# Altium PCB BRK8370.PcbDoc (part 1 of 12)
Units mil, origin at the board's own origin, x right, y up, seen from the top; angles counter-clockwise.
Board outline 8267.72 x 5708.66 mil, 6 copper layers (L1-TOP, L2-GND, L3-PWR, L4-PWR, L5-GND, L6-BOT), stack 68.606 mil thick; 319 components, 516 nets, 2008 pads, 1743 vias.
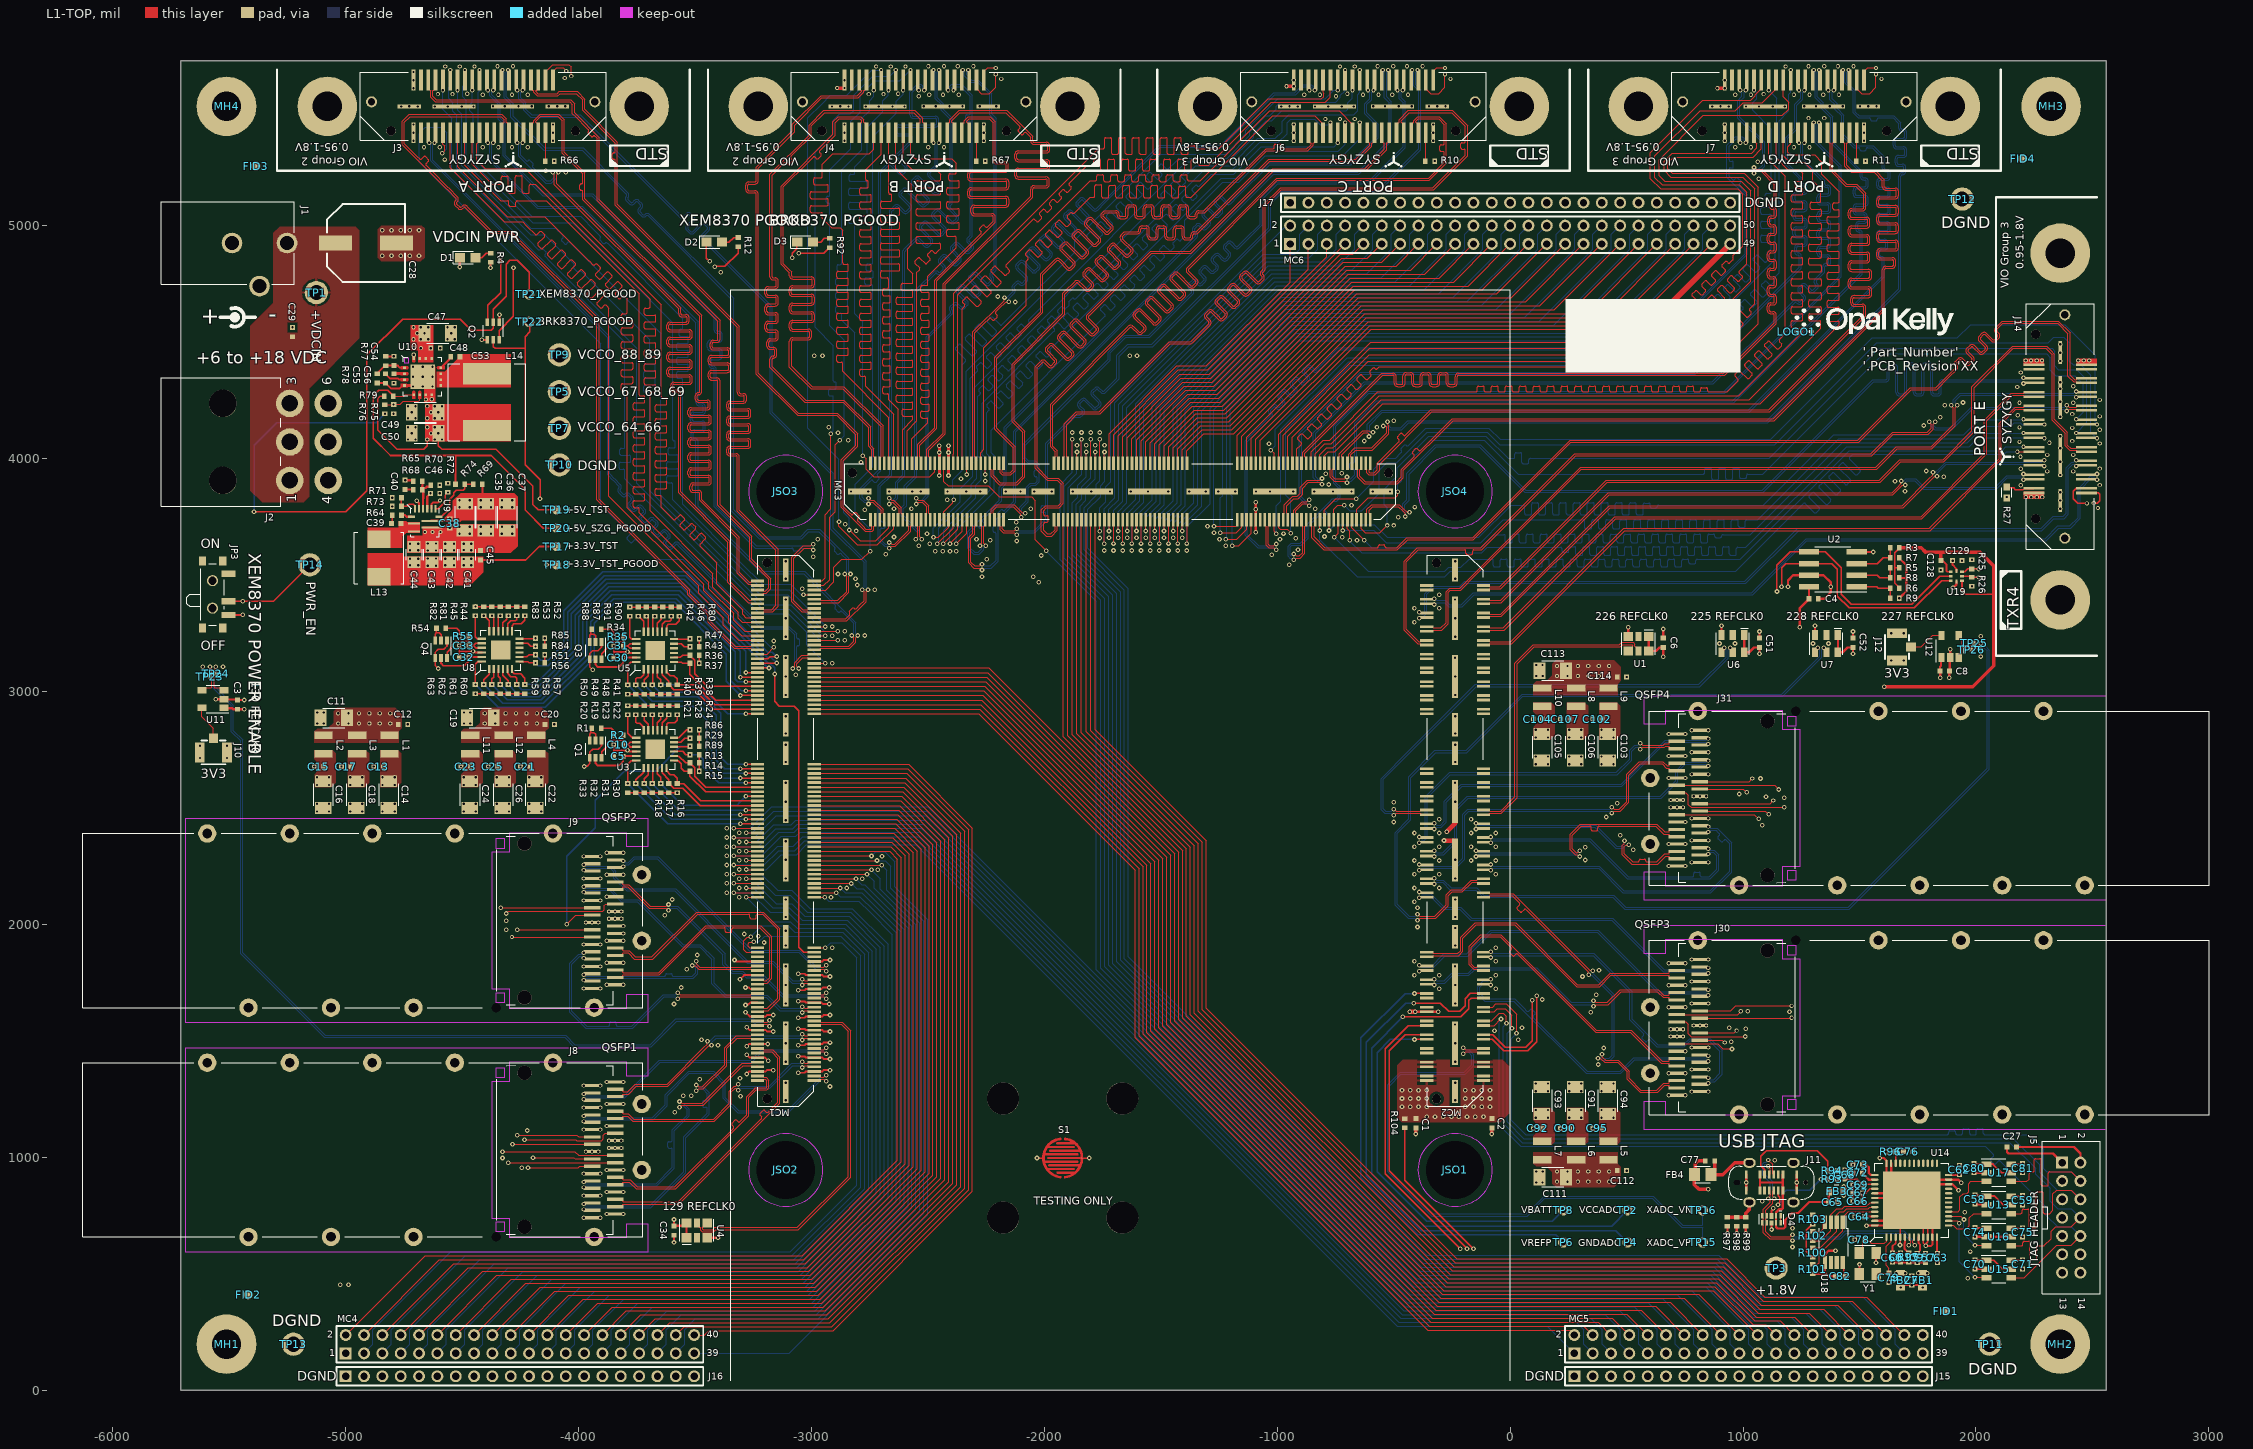
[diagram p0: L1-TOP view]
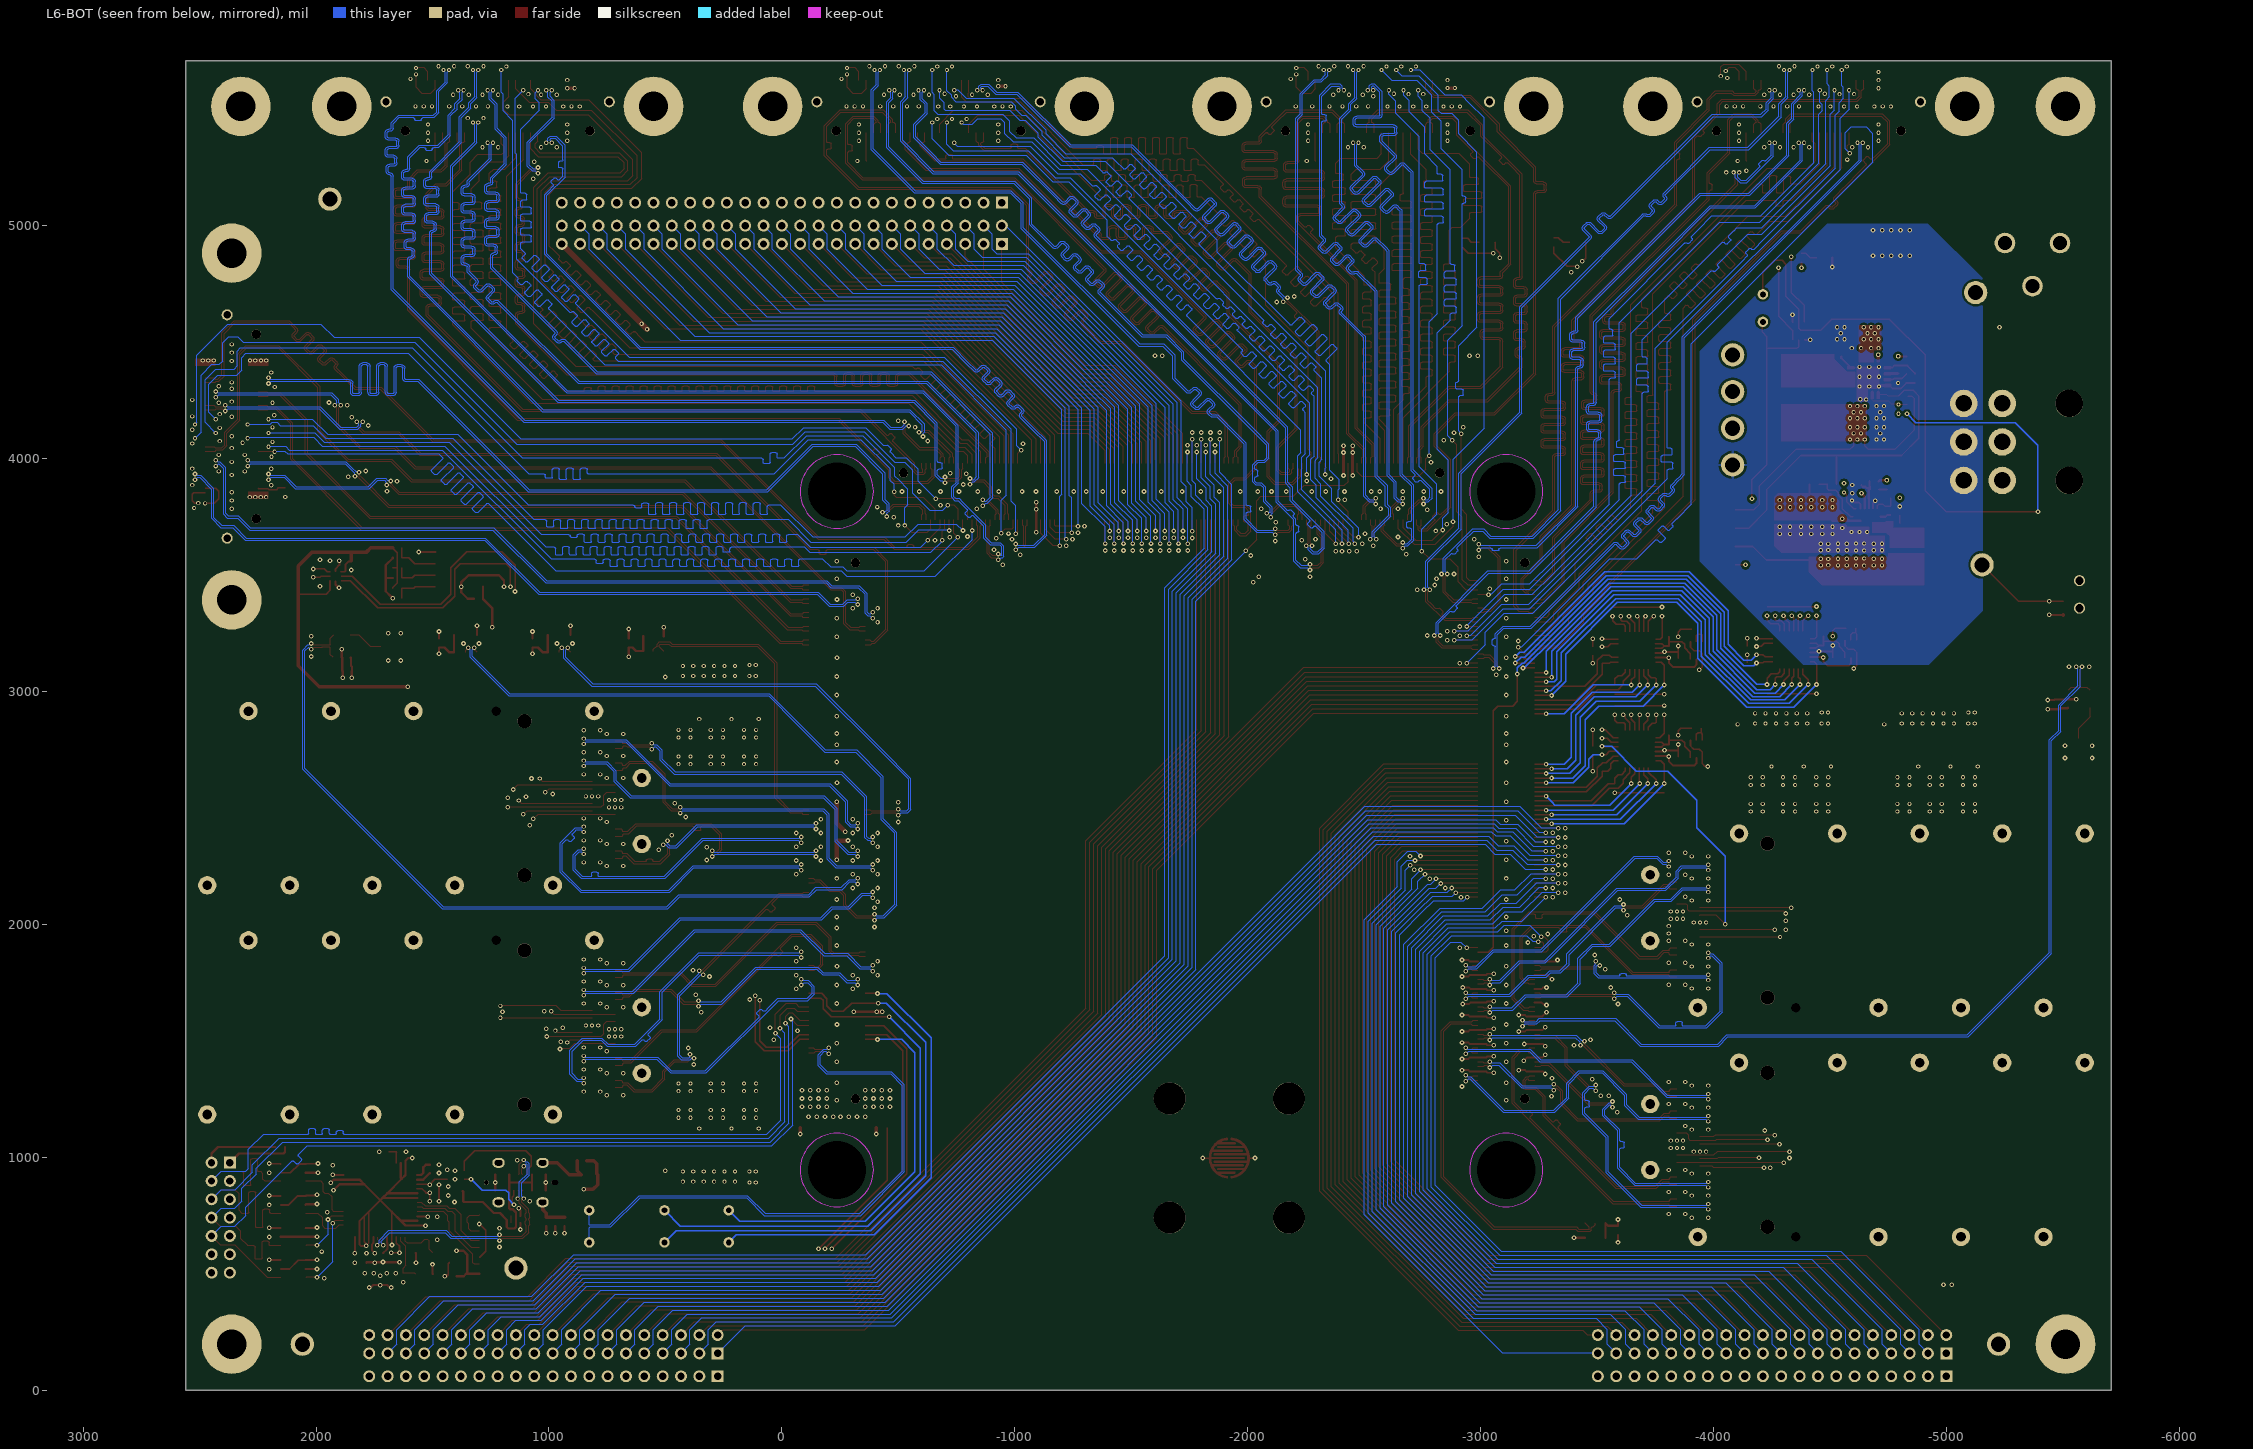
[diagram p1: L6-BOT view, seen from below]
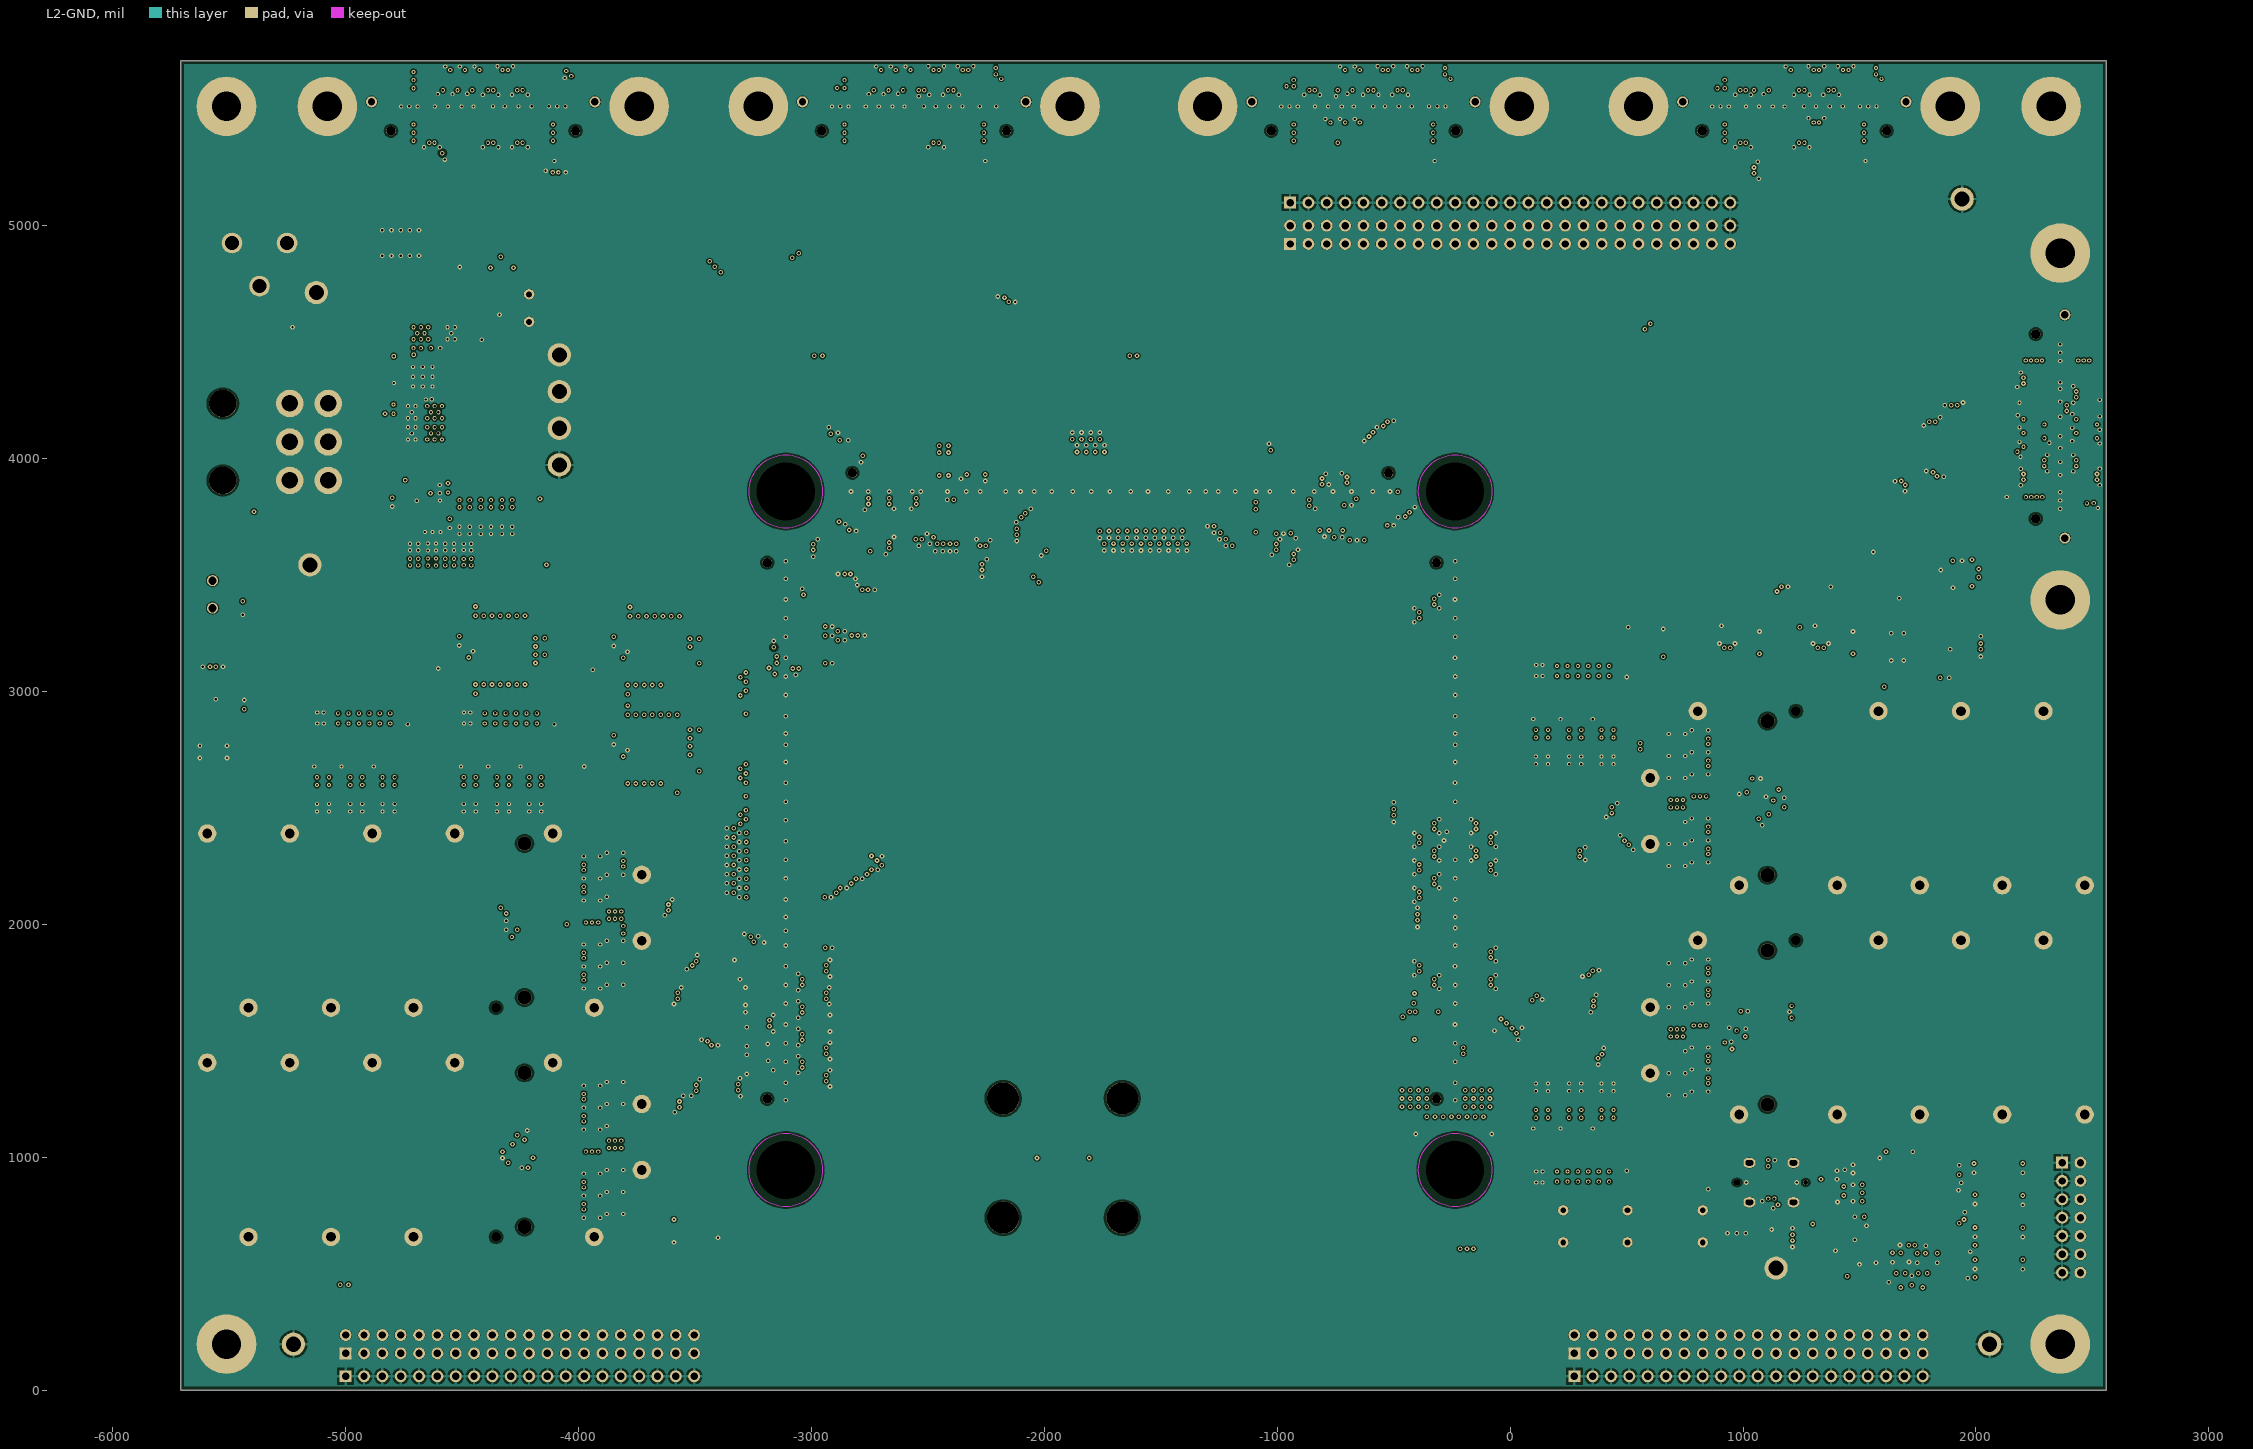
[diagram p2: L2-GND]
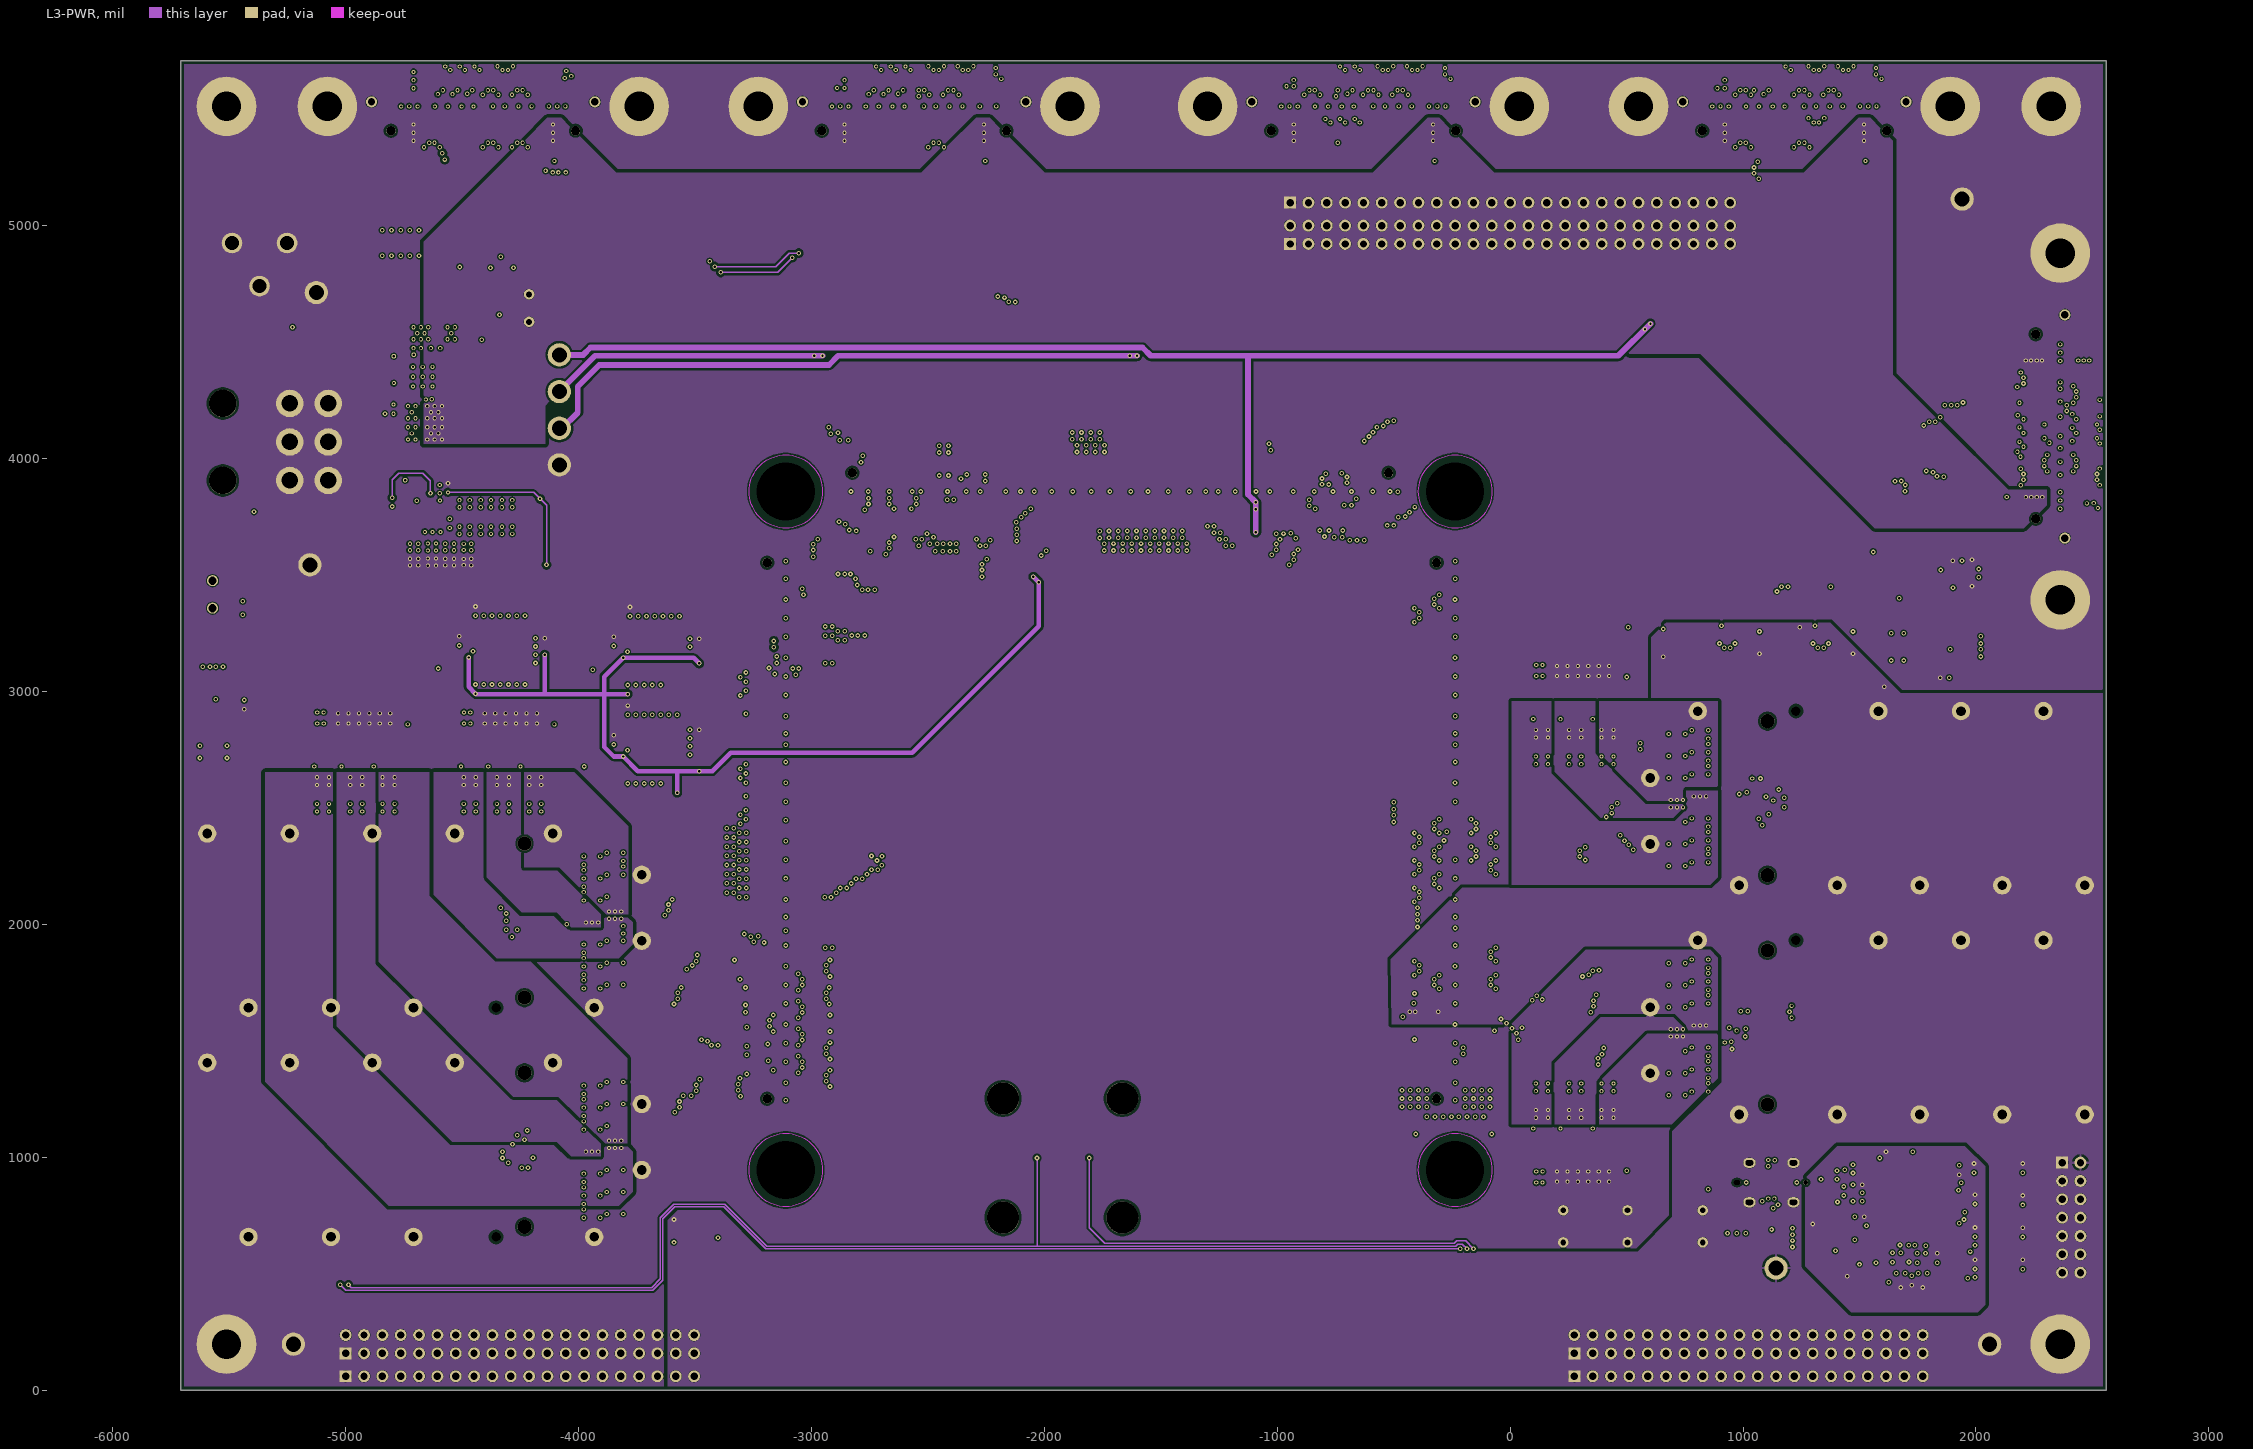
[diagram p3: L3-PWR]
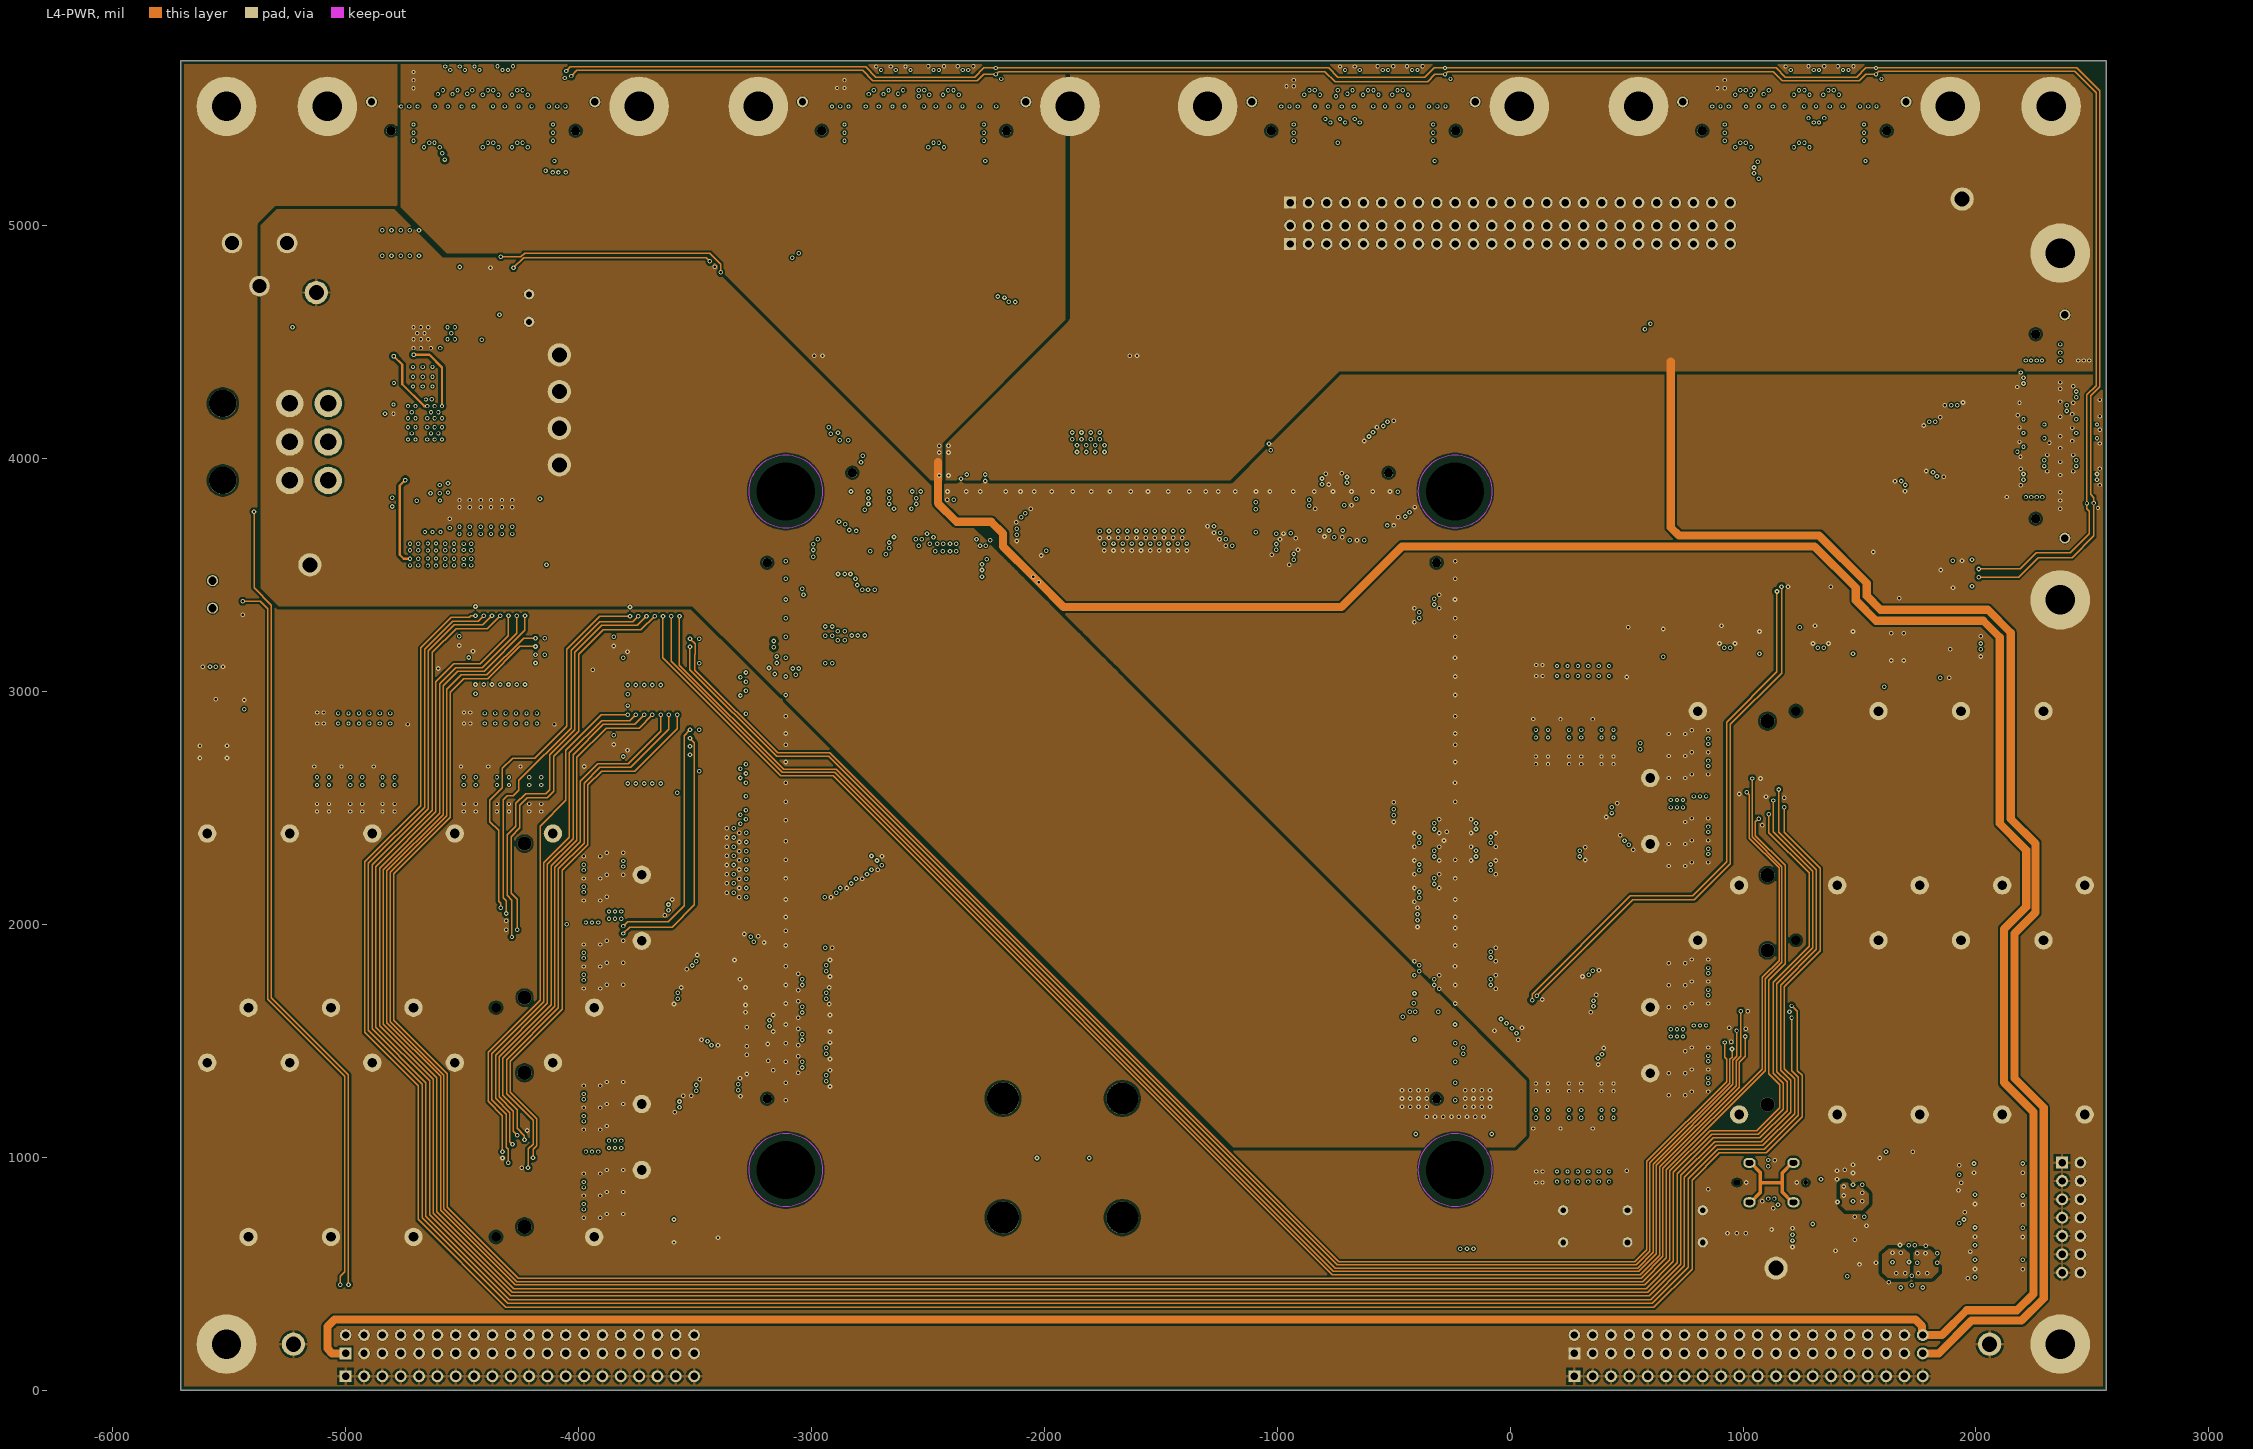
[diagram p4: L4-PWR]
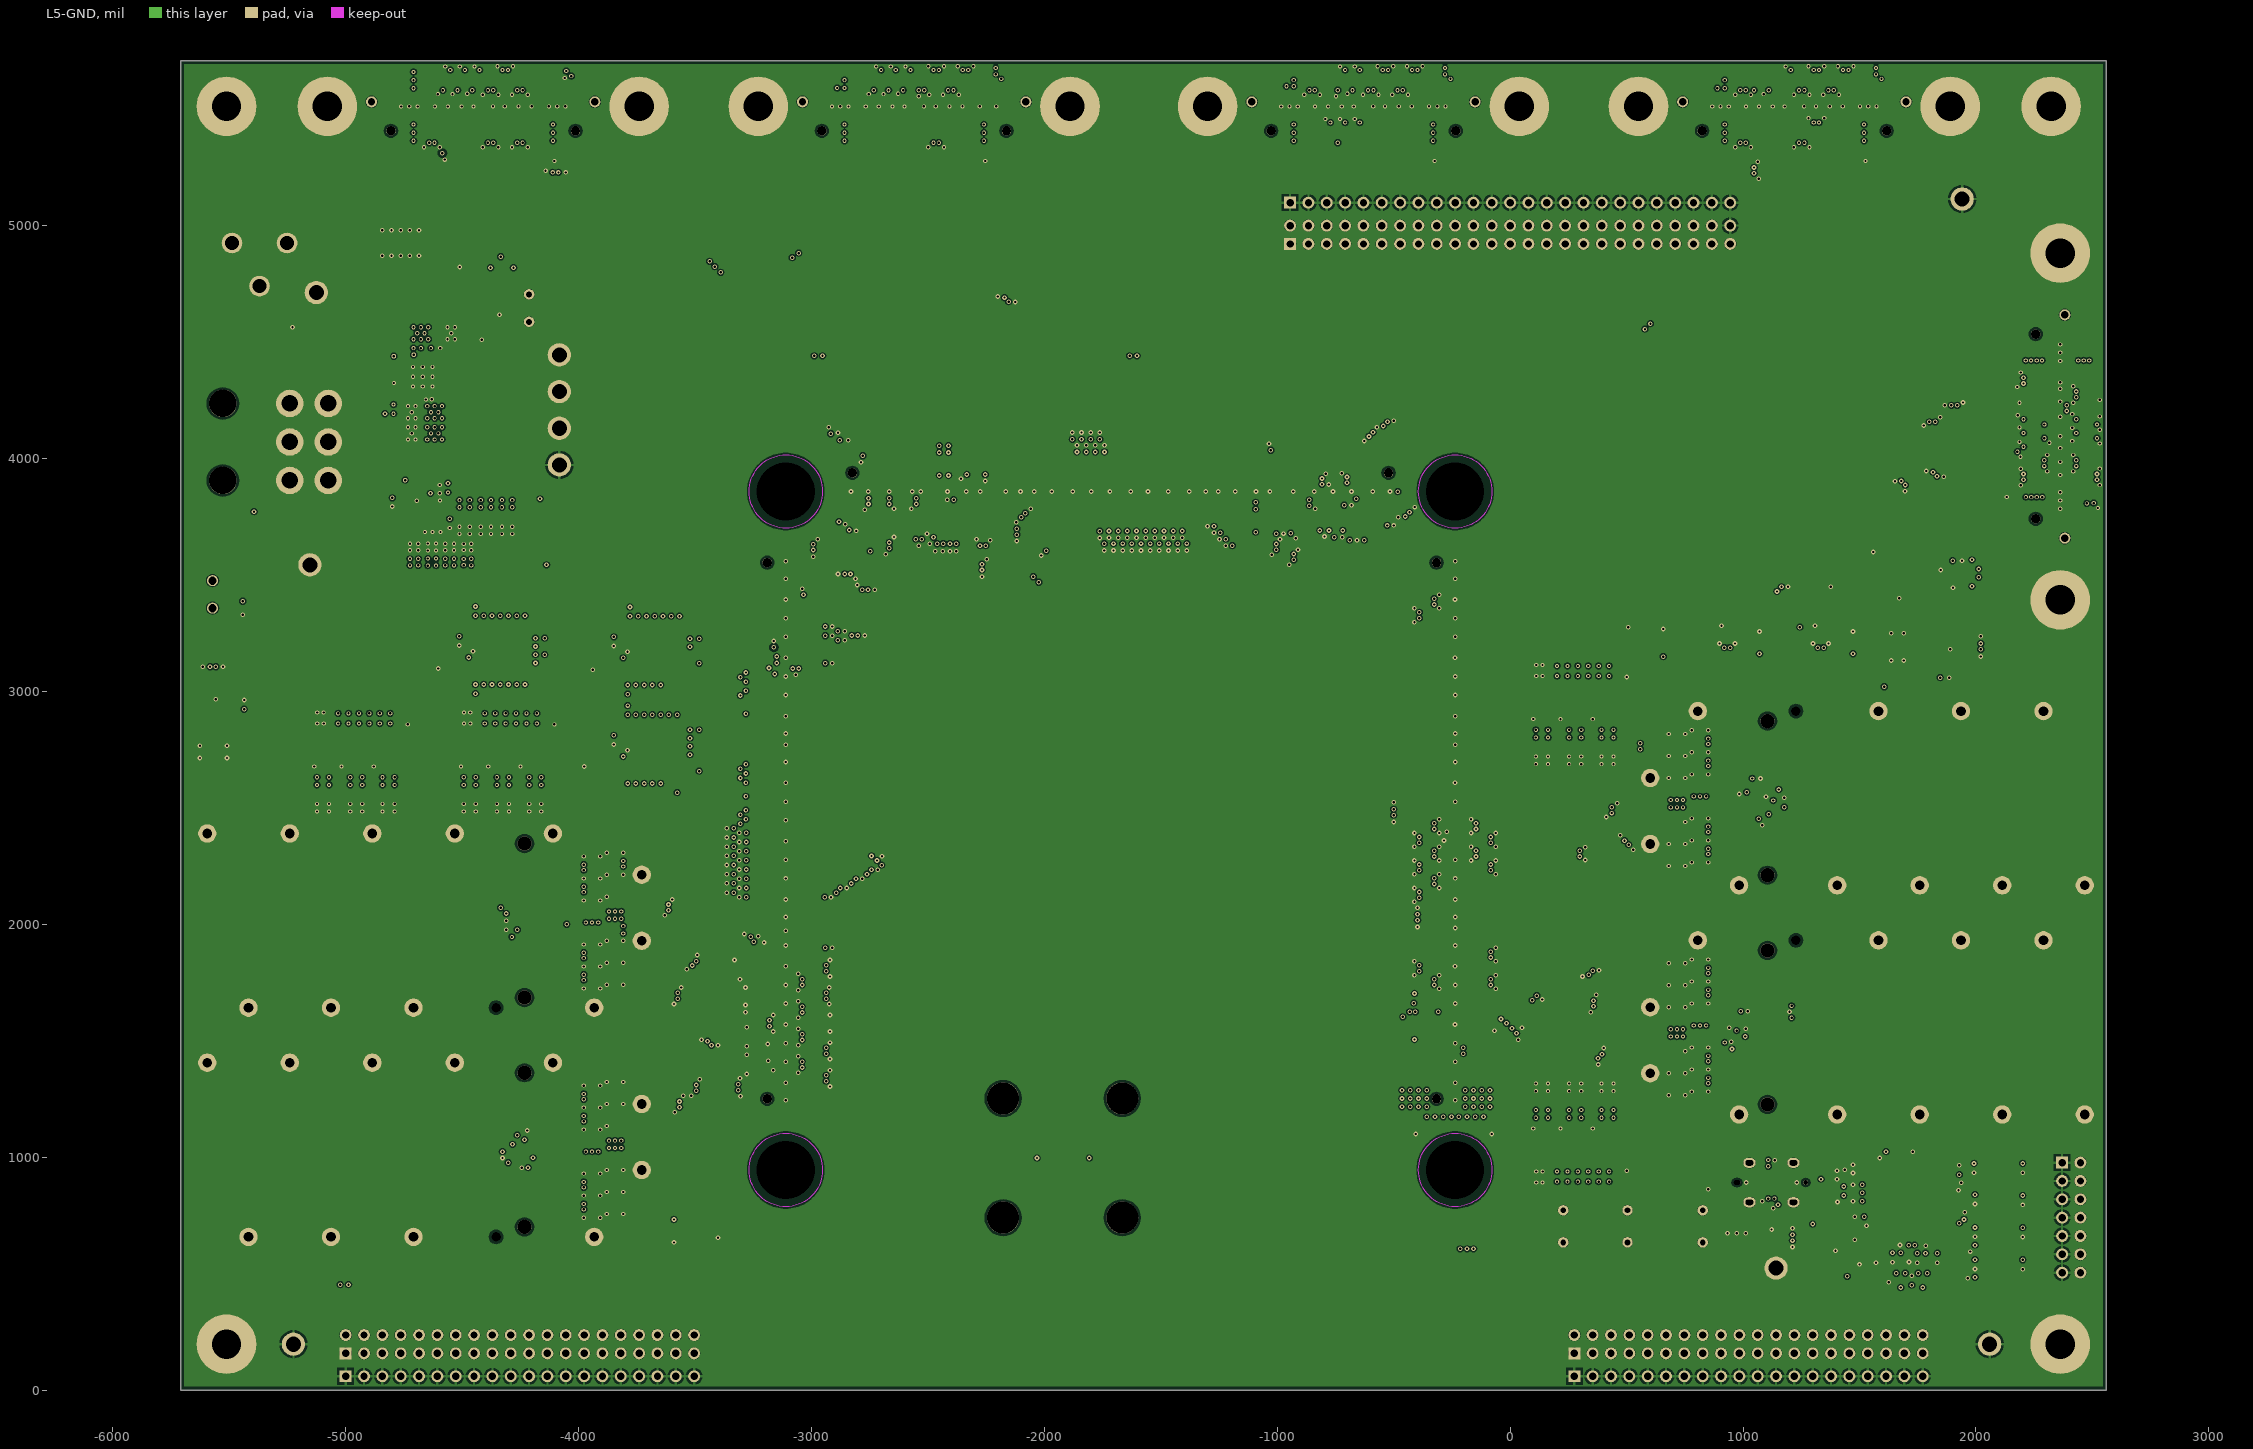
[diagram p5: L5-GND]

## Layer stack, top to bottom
Top Solder: solder mask 0.8, Solder Resist, Dk 0
L1-TOP: signal copper 1.4
Dielectric 1: prepreg 5.08, IT180A, Dk 3.79
L2-GND: signal copper 1.4
Dielectric 4: prepreg 2.8, PP-006, Dk 4.1
L3-PWR: signal copper 1.378
Dielectric 2: core 44.49, IT180A, Dk 4.35
L4-PWR: signal copper 1.378
Dielectric 5: prepreg 2.8, PP-006, Dk 4.1
L5-GND: signal copper 1.4
Dielectric 3: prepreg 5.08, PP-006, Dk 4.1
L6-BOT: signal copper 1.4
Solder Side: solder mask 0.8, Solder Resist, Dk 0

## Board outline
-5708.66,0 -5708.66,5708.66 2559.05,5708.66 2559.06,0

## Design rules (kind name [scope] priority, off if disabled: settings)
BoardOutlineClearance [All] p1: gap=15 ignorepadtopadclearanceinfootprint=FALSE
Clearance Clearance_SE_SE [InNetClass('50ohm') and not (TouchesRoom('MC2A') or TouchesRoom('MC1A') or TouchesRoom('PORTE') or TouchesRoom('PORTF') or TouchesRoom('PORTD') or TouchesRoom('PORTC') or TouchesRoom('PORTB') or TouchesRoom('PORTA') or TouchesRoom('MC1') or TouchesRoom('MC2')) vs InNetClass('50ohm') and not (TouchesRoom('MC2A') or TouchesRoom('MC1A') or TouchesRoom('PORTE') or TouchesRoom('PORTF') or TouchesRoom('PORTD') or TouchesRoom('PORTC') or TouchesRoom('PORTB') or TouchesRoom('PORTA') or TouchesRoom('MC1') or TouchesRoom('MC2'))] p1: gap=5 ignorepadtopadclearanceinfootprint=TRUE except(7.5: Via-Fill Via-Poly Via-Region; 8: Arc-Poly SMDPad-Poly THPad-Poly Fill-Poly Poly-Region Poly-Text Poly-Hole; 10: Track-Poly; 12: Arc-Arc Arc-Track Track-Track; 15: Poly-Poly)
Clearance Clearance_DIFF_DIFF [InDifferentialPairClass('100ohm_Diff') and not (TouchesRoom('MC3') or TouchesRoom('MC2A') or TouchesRoom('MC1A') or TouchesRoom('PORTE') or TouchesRoom('PORTF') or TouchesRoom('PORTD') or TouchesRoom('PORTC') or TouchesRoom('PORTB') or TouchesRoom('PORTA') or TouchesRoom('M.2') or HasFootprint('RESC1005X06A') or HasFootprint('CAPC1005X06A') or TouchesRoom('MC1') or TouchesRoom('MC2')) vs InDifferentialPairClass('100ohm_Diff') and not (TouchesRoom('MC3') or TouchesRoom('MC2A') or TouchesRoom('MC1A') or TouchesRoom('PORTE') or TouchesRoom('PORTF') or TouchesRoom('PORTD') or TouchesRoom('PORTC') or TouchesRoom('PORTB') or TouchesRoom('PORTA') or TouchesRoom('M.2') or HasFootprint('RESC1005X06A') or HasFootprint('CAPC1005X06A') or TouchesRoom('MC1') or TouchesRoom('MC2'))] p2: gap=25 ignorepadtopadclearanceinfootprint=TRUE
Clearance [All] p3: gap=5 ignorepadtopadclearanceinfootprint=FALSE except(7.5: Via-Fill Via-Region; 8: Poly-Region Poly-Text Poly-Hole; 10: Arc-Poly Track-Poly SMDPad-Poly THPad-Poly Via-Poly; 15: Fill-Poly Poly-Poly)
DiffPairsRouting 100ohm_Diff [InDifferentialPairClass('100ohm_Diff')] p1: maxlimit=5.7 minlimit=1 mostfreqgap=1 toplayer_mingap=5.7 toplayer_prefgap=5.7 toplayer_minwidth=3.3 toplayer_maxwidth=3.3 toplayer_prefwidth=3.3 midlayer1_maxgap=1 midlayer1_minwidth=1 midlayer1_maxwidth=1 midlayer1_prefwidth=1 midlayer2_maxgap=1 midlayer2_minwidth=1 midlayer2_maxwidth=1 midlayer2_prefwidth=1 midlayer3_maxgap=1 midlayer3_minwidth=1 midlayer3_maxwidth=1 midlayer3_prefwidth=1 midlayer6_maxgap=1 midlayer6_minwidth=1 midlayer6_maxwidth=1 midlayer6_prefwidth=1 bottomlayer_mingap=5.7 bottomlayer_prefgap=5.7 bottomlayer_minwidth=3.3 bottomlayer_maxwidth=3.3 bottomlayer_prefwidth=3.3 maxuncoupledlength=500
DiffPairsRouting 90ohm_Diff [InDifferentialPairClass('90ohm_Diff')] p2: maxlimit=6 minlimit=1 mostfreqgap=1 toplayer_mingap=6 toplayer_prefgap=6 toplayer_minwidth=4 toplayer_maxwidth=4 toplayer_prefwidth=4 midlayer1_maxgap=1 midlayer1_minwidth=1 midlayer1_maxwidth=1 midlayer1_prefwidth=1 midlayer2_maxgap=1 midlayer2_minwidth=1 midlayer2_maxwidth=1 midlayer2_prefwidth=1 midlayer3_maxgap=1 midlayer3_minwidth=1 midlayer3_maxwidth=1 midlayer3_prefwidth=1 midlayer6_maxgap=1 midlayer6_minwidth=1 midlayer6_maxwidth=1 midlayer6_prefwidth=1 bottomlayer_mingap=6 bottomlayer_prefgap=6 bottomlayer_minwidth=4 bottomlayer_maxwidth=4 bottomlayer_prefwidth=4 maxuncoupledlength=500
FabricationTestPointUsage TestPointUsage [All] p1: valid=0 allowmultiple=FALSE
FabricationTestpoint Testpoint [All] p1: side=3 testpointundercomponent=TRUE minsize=40 maxsize=100 preferedsize=60 minholesize=0 maxholesize=40 preferedholesize=32 testpointgrid=1 allowsidetop=TRUE allowsidebottom=TRUE usegrid=TRUE gridtolerance=0.01
HoleSize [All] p1: absolutevalues=TRUE maxlimit=500 minlimit=8 maxpercent=80.000 minpercent=20.000
MatchedLengths MatchedLengths_PORTA [InxSignalClass('PORTA')] p1: tolerance=10 checknetsindiffpair=FALSE checkdiffpairvsdiffpair=TRUE checkxsignals=TRUE checkothers=TRUE
MatchedLengths MatchedLengths_PORTB [InxSignalClass('PORTB')] p2: tolerance=10 checknetsindiffpair=FALSE checkdiffpairvsdiffpair=TRUE checkxsignals=TRUE checkothers=TRUE
MatchedLengths MatchedLengths_PORTC [InxSignalClass('PORTC')] p3: tolerance=10 checknetsindiffpair=FALSE checkdiffpairvsdiffpair=TRUE checkxsignals=TRUE checkothers=TRUE
MatchedLengths MatchedLengths_PORTD [InxSignalClass('PORTD')] p4: tolerance=10 checknetsindiffpair=FALSE checkdiffpairvsdiffpair=TRUE checkxsignals=TRUE checkothers=TRUE
MatchedLengths MatchedLengths_PORTE [InxSignalClass('PORTE')] p5: tolerance=10 checknetsindiffpair=FALSE checkdiffpairvsdiffpair=TRUE checkxsignals=TRUE checkothers=TRUE
MatchedLengths MatchedLengths_JTAG [InxSignalClass('JTAG')] p6: tolerance=10 checknetsindiffpair=FALSE checkdiffpairvsdiffpair=TRUE checkxsignals=TRUE checkothers=TRUE
MatchedLengths okMatched_xSignals [InxSignalClass('All xSignals')] p7: tolerance=5 checknetsindiffpair=TRUE checkdiffpairvsdiffpair=FALSE checkxsignals=FALSE checkothers=FALSE
MinimumAnnularRing [All] p1: minimumring=3.25
MinimumSolderMaskSliver [All] p1: minsoldermaskwidth=2
PlaneClearance [All] p1: clearance=12
PlaneConnect [All] p1: planeconnectstyle=Direct reliefexpansion=20 reliefentries=4 reliefconductorwidth=10 reliefairgap=10
PolygonConnect ViaNoConnectPoly [Name Like 'Free-ViaNoConnect*'] p1: connectstyle=NoConnect reliefconductorwidth=10 reliefentries=4 polygonreliefangle="90 Angle" airgapwidth=10
PolygonConnect PolygonConnect_ReliefConnect [InComponent('MC1') or InComponent('MC2') or InComponent('MC3')] p2: connectstyle=Relief reliefconductorwidth=12 reliefentries=4 polygonreliefangle="90 Angle" airgapwidth=12
PolygonConnect PolygonConnect_DirectConnect [InComponent('J1') or InComponent('J2')] p3: connectstyle=Direct reliefconductorwidth=12 reliefentries=4 polygonreliefangle="90 Angle" airgapwidth=12
PolygonConnect "Via Connect" [IsVia] p4: connectstyle=Direct reliefconductorwidth=10 reliefentries=4 polygonreliefangle="90 Angle" airgapwidth=10
PolygonConnect PolygonConnect_TH [IsThruPin] p5: connectstyle=Relief reliefconductorwidth=12 reliefentries=4 polygonreliefangle="90 Angle" airgapwidth=10
PolygonConnect [All] p6: connectstyle=Direct reliefconductorwidth=12 reliefentries=4 polygonreliefangle="90 Angle" airgapwidth=12
ReturnPath [(InDifferentialPairClass('All Differential Pairs') or InNetClass('50ohm'))] p1: impedanceprofileid={63E3B4E6-A57D-433B-8A18-03E25DE6B9A2} _gaplimit=0 _useantipads=TRUE
RoomDefinition PORTA [False] p1: confinementstyle=ConfineIn formatcopy=TRUE lockcomponents=FALSE outline -4805.12,5696.85 -4012.8,5696.85 -4012.8,5308.07 -4805.12,5308.07
RoomDefinition PORTD [False] p2: confinementstyle=ConfineIn formatcopy=TRUE lockcomponents=FALSE outline 824.75,5696.85 1617.08,5696.85 1617.08,5308.07 824.75,5308.07
RoomDefinition PORTC [False] p3: confinementstyle=ConfineIn formatcopy=TRUE lockcomponents=FALSE outline -1025.64,5696.85 -233.32,5696.85 -233.32,5308.07 -1025.64,5308.07
RoomDefinition PORTB [False] p4: confinementstyle=ConfineIn formatcopy=TRUE lockcomponents=FALSE outline -2954.72,5696.85 -2162.4,5696.85 -2162.4,5308.07 -2954.72,5308.07
RoomDefinition MC3 [False] p5: confinementstyle=ConfineIn formatcopy=TRUE lockcomponents=FALSE outline -2843.13,3665.35 -2843.13,4055.12 -503.36,4055.12 -503.36,3665.35
RoomDefinition MC1 [False] p6: confinementstyle=ConfineIn formatcopy=TRUE lockcomponents=FALSE outline -3307.09,1291.34 -3307.09,3571.46 -2935.44,3571.46 -2935.44,1291.34
RoomDefinition MC2 [False] p7: confinementstyle=ConfineIn formatcopy=TRUE lockcomponents=FALSE outline -433.07,1291.34 -433.07,3502.56 -61.42,3502.56 -61.42,1291.34
RoomDefinition PORTE [False] p8: confinementstyle=ConfineIn formatcopy=TRUE lockcomponents=FALSE outline 2535.31,4464.28 2535.31,3794.99 2184.92,3794.99 2184.92,4464.28
RoutingLayers [All] p1: top layer_v5=TRUE mid layer 1_v5=TRUE mid layer 2_v5=TRUE mid layer 3_v5=TRUE mid layer 6_v5=FALSE bottom layer_v5=TRUE
RoutingVias [All] p1: holewidth=8 width=16 viastyle="Through Hole" minholewidth=8 minwidth=16 maxholewidth=50 maxwidth=100
SilkToSilkClearance [All] p1: silktosilkclearance=0.1
SilkToSolderMaskClearance SilkscreenOverComponentPads [IsPad] p1: minsilkscreentomaskgap=8 clearancetoexposedcopper=FALSE
SolderMaskExpansion [All] p1: expansion=2 istentingtop=FALSE
ViasUnderSMD [All] p1: allowed=TRUE
Width Width50ohm [InNetClass('50ohm')] p1: maxlimit=4.96 minlimit=1 preferedwidth=1 toplayer_minwidth=4.96 toplayer_prefwidth=4.96 midlayer1_maxwidth=1 midlayer2_maxwidth=1 midlayer3_maxwidth=1 midlayer6_maxwidth=1 bottomlayer_minwidth=4.96 bottomlayer_prefwidth=4.96 minimp=50.000000 maximp=50.000000 favimp=50.000000
Width okWidth [All] p2: maxlimit=150 minlimit=4 preferedwidth=7 minimp=50.000000 maximp=50.000000 favimp=50.000000
20 further rules are at their usual default settings.

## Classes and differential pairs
differential pair class 90ohm_Diff: DP_USB_JTAG
component class JTAG: C4 C7 C9 C57 C58 C59 C60 C61 C62 C63 C64 C65 C66 C67 C68 C69 C70 C71 C72 C73 C74 C75 C76 C77 C78 C79 C80 C81 C82 D4 FB1 FB2 FB3 FB4 J5 J11 R93 R94 R95 R96 R97 R98 R99 R100 R101 R102 R103 U13 U14 U15 U16 U17 U18 Y1
differential pair class 100ohm_Diff: D_PORTA_P2C_ D_PORTB_P2C_ D_PORTC_P2C_ D_PORTD_P2C_ D_PORTE_P2C_ DP_MGTHRX0_225 DP_MGTHRX0_226 DP_MGTHRX1_225 DP_MGTHRX1_226 DP_MGTHRX2_225 DP_MGTHRX2_226 DP_MGTHRX3_225 DP_MGTHRX3_226 DP_MGTHTX0_225 DP_MGTHTX0_226 DP_MGTHTX1_225 DP_MGTHTX1_226 DP_MGTHTX2_225 DP_MGTHTX2_226 DP_MGTHTX3_225 DP_MGTHTX3_226 DP_MGTREFCLK0_129 DP_MGTREFCLK0_130 DP_MGTREFCLK0_225 DP_MGTREFCLK0_226 DP_MGTREFCLK0_227 DP_MGTREFCLK0_228 DP_PORTA_C2P_CLK DP_PORTA_D0 DP_PORTA_D1 DP_PORTA_D2 DP_PORTA_D3 DP_PORTA_D4 DP_PORTA_D5 DP_PORTA_D6 DP_PORTA_D7 DP_PORTB_C2P_CLK DP_PORTB_D0 DP_PORTB_D1 DP_PORTB_D2 DP_PORTB_D3 DP_PORTB_D4 DP_PORTB_D5 DP_PORTB_D6 DP_PORTB_D7 DP_PORTC_C2P_CLK DP_PORTC_D0 DP_PORTC_D1 DP_PORTC_D2 DP_PORTC_D3 DP_PORTC_D4 DP_PORTC_D5 DP_PORTC_D6 DP_PORTC_D7 DP_PORTD_C2P_CLK DP_PORTD_D0 DP_PORTD_D1 DP_PORTD_D2 DP_PORTD_D3 DP_PORTD_D4 DP_PORTD_D5 DP_PORTD_D6 DP_PORTD_D7 DP_PORTE_C2P_CLK DP_PORTE_REFCLK DP_PORTE_RX0 DP_PORTE_RX1 DP_PORTE_RX2 DP_PORTE_RX3 DP_PORTE_TX0 DP_PORTE_TX1 DP_PORTE_TX2 DP_PORTE_TX3 DP_QSFP_1_RX1 DP_QSFP_1_RX2 DP_QSFP_1_RX3 DP_QSFP_1_RX4 DP_QSFP_1_TX1 DP_QSFP_1_TX2 DP_QSFP_1_TX3 DP_QSFP_1_TX4 DP_QSFP_2_RX1 DP_QSFP_2_RX2 DP_QSFP_2_RX3 DP_QSFP_2_RX4 DP_QSFP_2_TX1 DP_QSFP_2_TX2 DP_QSFP_2_TX3 DP_QSFP_2_TX4 DP_QSFP_3_RX1 DP_QSFP_3_RX2 DP_QSFP_3_RX3 DP_QSFP_3_RX4 DP_QSFP_3_TX1 DP_QSFP_3_TX2 DP_QSFP_3_TX3 DP_QSFP_3_TX4 DP_QSFP_4_RX1 DP_QSFP_4_RX2 DP_QSFP_4_RX3 DP_QSFP_4_RX4 DP_QSFP_4_TX1 DP_QSFP_4_TX2 DP_QSFP_4_TX3 DP_QSFP_4_TX4 DP_XADC_V_C
component class Power: C35 C36 C37 C38 C39 C40 C41 C42 C43 C44 C45 C46 C47 C48 C49 C50 C53 C54 C55 C56 L13 L14 R64 R65 R68 R69 R70 R71 R72 R73 R74 R75 R76 R77 R78 R79 R104 S1 TP17 TP18 TP19 TP20 U9 U10
component class "QSFP GTY": C11 C12 C13 C14 C15 C16 C17 C18 C19 C20 C21 C22 C23 C24 C25 C26 J8 J9 L1 L2 L3 L4 L11 L12 QSFP1 QSFP2 R19 R20 R21 R22 R23 R24 R28 R29 R86 R87 R88 R89 R90 R91
component class "QSFP GTH": C90 C91 C92 C93 C94 C95 C102 C103 C104 C105 C106 C107 C111 C112 C113 C114 J30 J31 L5 L6 L7 L8 L9 L10 QSFP3 QSFP4 R42 R43 R44 R45 R46 R47 R52 R53 R80 R81 R82 R83 R84 R85
component class MC3: J4 J6 J7 J15 J17 MC3 MC5 MC6 R10 R11 R67
component class MC2: C1 C2 C6 C8 C27 C51 C52 C128 C129 J12 J14 JP3 MC2 R3 R5 R6 R7 R8 R9 R25 R26 R27 TP14 TP15 TP16 TP25 TP26 U1 U2 U6 U7 U12 U19
component class MC1: C3 C5 C10 C30 C31 C32 C33 C34 J3 J10 J16 MC1 MC4 Q1 Q3 Q4 R1 R2 R13 R14 R15 R16 R17 R18 R30 R31 R32 R33 R34 R35 R36 R37 R38 R39 R40 R41 R48 R49 R50 R51 R54 R55 R56 R57 R58 R59 R60 R61 R62 R63 R66 TP23 TP24 U3 U4 U5 U8 U11
component class Top: ASSY1 C28 C29 D1 D2 D3 FID1 FID2 FID3 FID4 J1 J2 JSO1 JSO2 JSO3 JSO4 LABEL1 LOGO1 MH1 MH2 MH3 MH4 PCB1 Q2 R4 R12 R92 TP1 TP2 TP3 TP4 TP5 TP6 TP7 TP8 TP9 TP10 TP11 TP12 TP13 TP21 TP22
net class 50ohm: B64_L1N B64_L1P B64_L5N B64_L5P B64_L6N B64_L6P B64_L7N B64_L7P B64_L9N B64_L9P B64_L16N B64_L16P B64_L18N B64_L18P B64_L20N B64_L20P B64_T0U_N12_VRP B68_L1N B68_L1P B68_L2N B68_L2P B68_L3N B68_L3P B68_L6N B68_L6P B68_L7N B68_L7P B68_L8N B68_L8P B68_L9N B68_L9P B68_L10N B68_L10P B68_L11N B68_L11P B68_L12N B68_L12P B68_L13N B68_L13P B68_L14N B68_L14P B68_L15N B68_L15P B68_L16N B68_L16P B68_L17N B68_L17P B68_L18N B68_L18P B68_L19N B68_L19P B68_L20N B68_L20P B68_L22N B68_L22P B68_L23N B68_L23P B68_T0U_N12_VRP B68_T1U_N12 B68_T2U_N12 B69_L3P B69_L5N B69_L5P B69_L11N B69_L11P B69_L14N B69_L14P B69_L16N B69_L16P B69_L20N B69_L20P B69_L21N B69_L21P B69_L23N B69_L23P B69_L24N B69_L24P B88_L1N B88_L1P B88_L2N B88_L2P B88_L3N B88_L3P B88_L4N B88_L4P B88_L5N B88_L5P B88_L6N B88_L6P B88_L7N B88_L7P B88_L8N B88_L8P B88_L9N B88_L9P B88_L10N B88_L10P B88_L11N B88_L11P B88_L12N B88_L12P B89_L1N B89_L1P B89_L2N B89_L2P B89_L3N B89_L3P B89_L4N B89_L4P B89_L5N B89_L5P B89_L6N B89_L6P B89_L7N B89_L7P B89_L8N B89_L8P B89_L9N B89_L9P B89_L10N B89_L10P B89_L11N B89_L11P B89_L12N B89_L12P FPGA_JTAG_TCK FPGA_JTAG_TDI FPGA_JTAG_TDO FPGA_JTAG_TMS FTDI_TCK FTDI_TDI FTDI_TDO FTDI_TMS MGTREFCLK0_130 MGTREFCLK0_227 PORTA_S16 PORTA_S17 PORTA_S18 PORTA_S19 PORTA_S20 PORTA_S21 PORTA_S22 PORTA_S23 PORTA_S24 PORTA_S25 PORTA_S26 PORTA_S27 PORTB_S16 PORTB_S17 PORTB_S18 PORTB_S19 PORTB_S20 PORTB_S21 PORTB_S22 PORTB_S23 PORTB_S24 PORTB_S25 PORTB_S26 PORTB_S27 PORTC_S16 PORTC_S17 PORTC_S18 PORTC_S19 PORTC_S20 PORTC_S21 PORTC_S22 PORTC_S23 PORTC_S24 PORTC_S25 PORTC_S26 PORTC_S27 PORTD_S16 PORTD_S17 PORTD_S18 PORTD_S19 PORTD_S20 PORTD_S21 PORTD_S22 PORTD_S23 PORTD_S24 PORTD_S25 PORTD_S26 PORTD_S27 PORTE_S0 PORTE_S1 PORTE_S2 PORTE_S3 PORTE_S4 PORTE_S5 PORTE_S6 PORTE_S7 PORTE_S8 PORTE_S9
net class Power: +1.8V +VDCIN VBATT
differential pair DP_USB_JTAG: +USB_DP -USB_DN
differential pair DP_PORTA_D0: +PORTA_S0_D0_P -PORTA_S2_D0_N
differential pair DP_PORTA_D2: +PORTA_S4_D2_P -PORTA_S6_D2_N
differential pair DP_PORTA_D3: +PORTA_S5_D3_P -PORTA_S7_D3_N
differential pair DP_PORTA_D4: +PORTA_S8_D4_P -PORTA_S10_D4_N
differential pair DP_PORTA_D5: +PORTA_S9_D5_P -PORTA_S11_D5_N
differential pair DP_PORTA_D6: +PORTA_S12_D6_P -PORTA_S14_D6_N
differential pair DP_PORTA_D7: +PORTA_S13_D7_P -PORTA_S15_D7_N
differential pair DP_PORTB_D0: +PORTB_S0_D0_P -PORTB_S2_D0_N
differential pair DP_PORTB_D1: +PORTB_S1_D1_P -PORTB_S3_D1_N
differential pair DP_PORTB_D2: +PORTB_S4_D2_P -PORTB_S6_D2_N
differential pair DP_PORTB_D3: +PORTB_S5_D3_P -PORTB_S7_D3_N
differential pair DP_PORTB_D4: +PORTB_S8_D4_P -PORTB_S10_D4_N
differential pair DP_PORTB_D5: +PORTB_S9_D5_P -PORTB_S11_D5_N
differential pair DP_PORTB_D6: +PORTB_S12_D6_P -PORTB_S14_D6_N
differential pair DP_PORTB_D7: +PORTB_S13_D7_P -PORTB_S15_D7_N
differential pair DP_PORTC_D0: +PORTC_S0_D0_P -PORTC_S2_D0_N
differential pair DP_PORTC_D1: +PORTC_S1_D1_P -PORTC_S3_D1_N
differential pair DP_PORTC_D2: +PORTC_S4_D2_P -PORTC_S6_D2_N
differential pair DP_PORTC_D3: +PORTC_S5_D3_P -PORTC_S7_D3_N
differential pair DP_PORTC_D4: +PORTC_S8_D4_P -PORTC_S10_D4_N
differential pair DP_PORTC_D5: +PORTC_S9_D5_P -PORTC_S11_D5_N
differential pair DP_PORTC_D6: +PORTC_S12_D6_P -PORTC_S14_D6_N
differential pair DP_PORTC_D7: +PORTC_S13_D7_P -PORTC_S15_D7_N
differential pair DP_PORTD_D0: +PORTD_S0_D0_P -PORTD_S2_D0_N
differential pair DP_PORTD_D1: +PORTD_S1_D1_P -PORTD_S3_D1_N
differential pair DP_PORTD_D2: +PORTD_S4_D2_P -PORTD_S6_D2_N
differential pair DP_PORTD_D3: +PORTD_S5_D3_P -PORTD_S7_D3_N
differential pair DP_PORTD_D4: +PORTD_S8_D4_P -PORTD_S10_D4_N
differential pair DP_PORTD_D5: +PORTD_S9_D5_P -PORTD_S11_D5_N
differential pair DP_PORTD_D6: +PORTD_S12_D6_P -PORTD_S14_D6_N
differential pair DP_PORTD_D7: +PORTD_S13_D7_P -PORTD_S15_D7_N
differential pair DP_PORTA_D1: +PORTA_S1_D1_P -PORTA_S3_D1_N
differential pair D_PORTE_P2C_: +PORTE_P2C_CLK_N -PORTE_P2C_CLK_P
differential pair D_PORTA_P2C_: +PORTA_P2C_CLK_N -PORTA_P2C_CLK_P
differential pair D_PORTB_P2C_: +PORTB_P2C_CLK_N -PORTB_P2C_CLK_P
differential pair D_PORTC_P2C_: +PORTC_P2C_CLK_N -PORTC_P2C_CLK_P
differential pair D_PORTD_P2C_: +PORTD_P2C_CLK_N -PORTD_P2C_CLK_P
differential pair DP_XADC_V_C: +XADC_VN_C -XADC_VP_C
differential pair DP_MGTREFCLK0_129: +MGTREFCLK0N_129 -MGTREFCLK0P_129
differential pair DP_MGTREFCLK0_130: +MGTREFCLK0N_130 -MGTREFCLK0P_130
differential pair DP_MGTREFCLK0_225: +MGTREFCLK0N_225 -MGTREFCLK0P_225
differential pair DP_MGTREFCLK0_226: +MGTREFCLK0N_226 -MGTREFCLK0P_226
differential pair DP_MGTREFCLK0_227: +MGTREFCLK0N_227 -MGTREFCLK0P_227
differential pair DP_MGTREFCLK0_228: +MGTREFCLK0N_228 -MGTREFCLK0P_228
differential pair DP_MGTHRX0_226: +"" -""
differential pair DP_MGTHRX1_226: +"" -""
differential pair DP_MGTHRX2_226: +"" -""
differential pair DP_MGTHRX3_226: +"" -""
differential pair DP_MGTHTX0_226: +"" -""
differential pair DP_MGTHTX1_226: +"" -""
differential pair DP_MGTHTX2_226: +"" -""
differential pair DP_MGTHTX3_226: +"" -""
differential pair DP_MGTHRX0_225: +"" -""
differential pair DP_MGTHRX1_225: +"" -""
differential pair DP_MGTHRX2_225: +"" -""
differential pair DP_MGTHRX3_225: +"" -""
differential pair DP_MGTHTX0_225: +"" -""
differential pair DP_MGTHTX1_225: +"" -""
differential pair DP_MGTHTX2_225: +"" -""
differential pair DP_MGTHTX3_225: +"" -""
differential pair DP_PORTA_C2P_CLK: +PORTA_C2P_CLK_P -PORTA_C2P_CLK_N
differential pair DP_PORTB_C2P_CLK: +PORTB_C2P_CLK_P -PORTB_C2P_CLK_N
differential pair DP_PORTC_C2P_CLK: +PORTC_C2P_CLK_P -PORTC_C2P_CLK_N
differential pair DP_PORTD_C2P_CLK: +PORTD_C2P_CLK_P -PORTD_C2P_CLK_N
differential pair DP_QSFP_1_RX1: +QSFP_1_RX1_P -QSFP_1_RX1_N
differential pair DP_QSFP_1_RX2: +QSFP_1_RX2_P -QSFP_1_RX2_N
differential pair DP_QSFP_1_RX3: +QSFP_1_RX3_P -QSFP_1_RX3_N
differential pair DP_QSFP_1_RX4: +QSFP_1_RX4_P -QSFP_1_RX4_N
differential pair DP_QSFP_1_TX1: +QSFP_1_TX1_P -QSFP_1_TX1_N
differential pair DP_QSFP_1_TX2: +QSFP_1_TX2_P -QSFP_1_TX2_N
differential pair DP_QSFP_1_TX3: +QSFP_1_TX3_P -QSFP_1_TX3_N
differential pair DP_QSFP_1_TX4: +QSFP_1_TX4_P -QSFP_1_TX4_N
differential pair DP_QSFP_2_RX1: +QSFP_2_RX1_P -QSFP_2_RX1_N
differential pair DP_QSFP_2_RX2: +QSFP_2_RX2_P -QSFP_2_RX2_N
differential pair DP_QSFP_2_RX3: +QSFP_2_RX3_P -QSFP_2_RX3_N
differential pair DP_QSFP_2_RX4: +QSFP_2_RX4_P -QSFP_2_RX4_N
differential pair DP_QSFP_2_TX1: +QSFP_2_TX1_P -QSFP_2_TX1_N
differential pair DP_QSFP_2_TX2: +QSFP_2_TX2_P -QSFP_2_TX2_N
differential pair DP_QSFP_2_TX3: +QSFP_2_TX3_P -QSFP_2_TX3_N
differential pair DP_QSFP_2_TX4: +QSFP_2_TX4_P -QSFP_2_TX4_N
differential pair DP_QSFP_3_RX1: +QSFP_3_RX1_P -QSFP_3_RX1_N
differential pair DP_QSFP_3_RX2: +QSFP_3_RX2_P -QSFP_3_RX2_N
differential pair DP_QSFP_3_RX3: +QSFP_3_RX3_P -QSFP_3_RX3_N
differential pair DP_QSFP_3_RX4: +QSFP_3_RX4_P -QSFP_3_RX4_N
differential pair DP_QSFP_3_TX1: +QSFP_3_TX1_P -QSFP_3_TX1_N
differential pair DP_QSFP_3_TX2: +QSFP_3_TX2_P -QSFP_3_TX2_N
differential pair DP_QSFP_3_TX3: +QSFP_3_TX3_P -QSFP_3_TX3_N
differential pair DP_QSFP_3_TX4: +QSFP_3_TX4_P -QSFP_3_TX4_N
differential pair DP_QSFP_4_RX1: +QSFP_4_RX1_P -QSFP_4_RX1_N
differential pair DP_QSFP_4_RX2: +QSFP_4_RX2_P -QSFP_4_RX2_N
differential pair DP_QSFP_4_RX3: +QSFP_4_RX3_P -QSFP_4_RX3_N
differential pair DP_QSFP_4_RX4: +QSFP_4_RX4_P -QSFP_4_RX4_N
differential pair DP_QSFP_4_TX1: +QSFP_4_TX1_P -QSFP_4_TX1_N
differential pair DP_QSFP_4_TX2: +QSFP_4_TX2_P -QSFP_4_TX2_N
differential pair DP_QSFP_4_TX3: +QSFP_4_TX3_P -QSFP_4_TX3_N
differential pair DP_QSFP_4_TX4: +QSFP_4_TX4_P -QSFP_4_TX4_N
differential pair DP_PORTE_C2P_CLK: +PORTE_C2P_CLK_P -PORTE_C2P_CLK_N
differential pair DP_PORTE_REFCLK: +PORTE_REFCLK_P -PORTE_REFCLK_N
differential pair DP_PORTE_RX0: +PORTE_RX0_P -PORTE_RX0_N
differential pair DP_PORTE_RX1: +PORTE_RX1_P -PORTE_RX1_N
differential pair DP_PORTE_RX2: +PORTE_RX2_P -PORTE_RX2_N
differential pair DP_PORTE_RX3: +PORTE_RX3_P -PORTE_RX3_N
differential pair DP_PORTE_TX0: +PORTE_TX0_P -PORTE_TX0_N
differential pair DP_PORTE_TX1: +PORTE_TX1_P -PORTE_TX1_N
differential pair DP_PORTE_TX2: +PORTE_TX2_P -PORTE_TX2_N
differential pair DP_PORTE_TX3: +PORTE_TX3_P -PORTE_TX3_N

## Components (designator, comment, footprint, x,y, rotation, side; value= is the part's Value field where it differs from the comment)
C1 "TMK105BJ104KV-F" CAPC1005X06A#1 -404.74,1145.67 r270 top locked value="0.1 u"
C2 "TMK105BJ104KV-F" CAPC1005X06A#1 -78.74,1145.67 r270 top locked value="0.1 u"
C3 "SM-0402, 10%, 10v" CAPC1005X06A#1 -5463.72,2942.94 r270 top value="0.1 u"
C4 "SM-0402, 10%, 10v" CAPC1005X06A#1 1303.15,3397.64 r180 top value="0.1 u"
C5 "SM-0402, 10%, 10v" CAPC1005X06A#2 -3828.74,2720.47 r0 top value="0.1 u"
C6 "SM-0402, 10%, 10v" CAPC1005X06A#1 657.48,3208.66 r270 top value="0.1 u"
C7 "JMK105BBJ475MV-F" CAPC1005X06A#2 1724.41,470.47 r270 top value=4.7u
C8 "SM-0402, 10%, 10v" CAPC1005X06A#1 1866.14,3086.61 r180 top value="0.1 u"
C9 "JMK105BBJ475MV-F" CAPC1005X06A#2 1748.03,567.32 r90 top value=4.7u
C10 "SM-0402, 10%, 10v" CAPC1005X06A#2 -3828.74,2771.65 r0 top value="0.1 u"
C11 "SM-1206, 10%, 10v, X7R" CAPC3216N -5051.18,2885.83 r0 top value=22u
C12 "SM-0402, 10%, 10v" CAPC1005X06A#2 -4753.94,2858.27 r180 top value="0.1 u"
C13 "SM-0402, 10%, 10v" CAPC1005X06A#2 -4859.25,2677.17 r0 top value="0.1 u"
C14 "SM-1206, 10%, 10v, X7R" CAPC3216N -4815.94,2557.09 r90 top value=22u
C15 "SM-0402, 10%, 10v" CAPC1005X06A#2 -5114.95,2677.17 r0 top value="0.1 u"
C16 "SM-1206, 10%, 10v, X7R" CAPC3216N -5097.44,2557.09 r90 top value=22u
C17 "SM-0402, 10%, 10v" CAPC1005X06A#2 -4998.03,2677.17 r0 top value="0.1 u"
C18 "SM-1206, 10%, 10v, X7R" CAPC3216N -4954.72,2557.09 r90 top value=22u
C19 "SM-1206, 10%, 10v, X7R" CAPC3216N -4421.26,2885.83 r0 top value=22u
C20 "SM-0402, 10%, 10v" CAPC1005X06A#2 -4124.02,2858.27 r180 top value="0.1 u"
C21 "SM-0402, 10%, 10v" CAPC1005X06A#2 -4229.33,2677.17 r0 top value="0.1 u"
C22 "SM-1206, 10%, 10v, X7R" CAPC3216N -4186.02,2557.09 r90 top value=22u
C23 "SM-0402, 10%, 10v" CAPC1005X06A#2 -4485.03,2677.17 r0 top value="0.1 u"
C24 "SM-1206, 10%, 10v, X7R" CAPC3216N -4467.52,2557.09 r90 top value=22u
C25 "SM-0402, 10%, 10v" CAPC1005X06A#2 -4368.11,2677.17 r0 top value="0.1 u"
C26 "SM-1206, 10%, 10v, X7R" CAPC3216N -4324.8,2557.09 r90 top value=22u
C27 "C0402C104K8PACTU" CAPC1005X06A#1 2153.94,1043.31 r0 top value="0.1 u"
C28 "EEE-FK1E221P" CAPAE9083X70N -4913.39,4925.2 r0 top value=220u
C29 "TMK105BJ104KV-F" CAPC1005X06A#1 -5228.35,4542.91 r270 top value="0.1 u"
C30 "SM-0402, 10%, 10v" CAPC1005X06A#2 -3828.74,3143.7 r0 top value="0.1 u"
C31 "SM-0402, 10%, 10v" CAPC1005X06A#2 -3828.74,3194.88 r0 top value="0.1 u"
C32 "SM-0402, 10%, 10v" CAPC1005X06A#2 -4492.13,3145.67 r0 top value="0.1 u"
C33 "SM-0402, 10%, 10v" CAPC1005X06A#2 -4492.13,3196.85 r0 top value="0.1 u"
C34 "SM-0402, 10%, 10v" CAPC1005X06A#2 -3590.55,684.65 r90 top value="0.1 u"
C35 "LMK316AB7226KL-TR" CAPC3216N -4489.41,3748.63 r90 top value="22 u"
C36 "LMK316AB7226KL-TR" CAPC3216N -4398.2,3748.63 r90 top value="22 u"
C37 "LMK316AB7226KL-TR" CAPC3216N -4307.04,3748.72 r90 top value="22 u"
C38 "C0402C104K8PACTU" CAPC1005X06A#2 -4553.27,3720.96 r90 top value="0.1 u"
C39 "TMK105BJ104KV-F" CAPC1005X06A#2 -4783.03,3720.59 r0 top value="0.1 u"
C40 "C0402C680J5GAC7867" CAPC1005X06A#2 -4744.76,3887.11 r90 top value="68 p"
C41 "CL21A226MQQNNNE" CAPC2012X14N -4477.08,3587.59 r270 top value="22 u"
C42 "CL21A226MQQNNNE" CAPC2012X14N -4553.63,3587.59 r270 top value="22 u"
C43 "CL21A226MQQNNNE" CAPC2012X14N -4629.71,3587.59 r270 top value="22 u"
C44 "CL21A226MQQNNNE" CAPC2012X14N -4706.25,3587.59 r270 top value="22 u"
C45 "TMK105BJ104KV-F" CAPC1005X06A#2 -4421,3584.36 r270 top value="0.1 u"
C46 "EMK105BJ105KV-F" CAPC1005X06A#2 -4615.96,3850.36 r180 top value=1u
C47 "C3216X5R1V226M160AC" CAPC3216N -4604.25,4537.87 r180 top value="22 u"
C48 "TMK105BJ104KV-F" CAPC1005X06A#2 -4614.25,4473.87 r180 top value="0.1 u"
C49 "LMK316AB7226KL-TR" CAPC3216N -4659.25,4198.87 r0 top value=22u
C50 "LMK316AB7226KL-TR" CAPC3216N -4659.25,4107.87 r0 top value=22u
C51 "SM-0402, 10%, 10v" CAPC1005X06A#2 1070.87,3208.66 r270 top value="0.1 u"
C52 "SM-0402, 10%, 10v" CAPC1005X06A#2 1472.44,3208.66 r270 top value="0.1 u"
C53 "C0402C104K8PACTU" CAPC1005X06A#2 -4529.33,4436.87 r0 top value="0.1 u"
C54 "CBR04C100J5GAC" CAPC1005X06A#2 -4793.25,4419.26 r90 top value=10p
C55 "C0402C332K5RACTU" CAPC1005X06A#2 -4828.86,4343.47 r90 top value="3.3 n"
C56 "LMK105BJ105KV-F" CAPC1005X06A#2 -4793.25,4343.47 r90 top value=1u
C57 "C0402C104K8PACTU" CAPC1005X06A#2 1783.46,567.32 r90 top value="0.1 u"
C58 "C0402C104K8PACTU" CAPC1005X06A#2 1996.06,818.9 r90 top value="0.1 u"
C59 "C0402C104K8PACTU" CAPC1005X06A#2 2200.79,814.96 r90 top value="0.1 u"
C60 "JMK105BBJ475MV-F" CAPC1005X06A#2 1641.73,568.9 r90 top value=4.7u
C61 "C0402C104K8PACTU" CAPC1005X06A#2 1677.17,569.29 r90 top value="0.1 u"
C62 "C0402C104K8PACTU" CAPC1005X06A#2 1929.13,944.88 r270 top value="0.1 u"
C63 "C0402C104K8PACTU" CAPC1005X06A#2 1834.65,567.32 r90 top value="0.1 u"
C64 "C0402C104K8PACTU" CAPC1005X06A#2 1500,744.09 r0 top value="0.1 u"
C65 "C0402C103K4RACTU" CAPC1005X06A#2 1385.83,807.09 r180 top value="0.01 u"
C66 "JMK105BBJ475MV-F" CAPC1005X06A#2 1492.13,811.02 r0 top value=4.7u
C67 "C0402C104K8PACTU" CAPC1005X06A#2 1492.13,846.46 r0 top value="0.1 u"
C68 "JMK105BBJ475MV-F" CAPC1005X06A#2 1437.01,925.2 r270 top value=4.7u
C69 "C0402C104K8PACTU" CAPC1005X06A#2 1492.13,881.89 r0 top value="0.1 u"
C70 "C0402C104K8PACTU" CAPC1005X06A#2 1996.06,539.76 r90 top value="0.1 u"
C71 "C0402C104K8PACTU" CAPC1005X06A#2 2200.79,539.37 r90 top value="0.1 u"
C72 "C0402C104K8PACTU" CAPC1005X06A#2 1492.13,932.09 r0 top value="0.1 u"
C73 "C0402C104K8PACTU" CAPC1005X06A#2 1492.13,967.52 r0 top value="0.1 u"
C74 "C0402C104K8PACTU" CAPC1005X06A#2 1996.06,677.56 r90 top value="0.1 u"
C75 "C0402C104K8PACTU" CAPC1005X06A#2 2200.79,677.17 r90 top value="0.1 u"
C76 "C0402C103K4RACTU" CAPC1005X06A#2 1708.66,1023.62 r180 top value="0.01 u"
C77 "SM-0402, 10%, 10v" CAPC1005X06A#2 858.27,984.25 r0 top value="0.1 u"
C78 "C0402C180J5GACTU" CAPC1005X06A#2 1500,645.67 r0 top value="18 p"
C79 "C0402C180J5GACTU" CAPC1005X06A#2 1625.98,482.28 r90 top value="18 p"
C80 "C0402C104K8PACTU" CAPC1005X06A#2 1992.13,952.76 r90 top value="0.1 u"
C81 "C0402C104K8PACTU" CAPC1005X06A#2 2200.79,952.76 r90 top value="0.1 u"
C82 "C0402C104K8PACTU" CAPC1005X06A#2 1417.32,488.19 r0 top value="0.1 u"
C90 "SM-0402, 10%, 10v" CAPC1005X06A#2 236.01,1123.13 r0 top value="0.1 u"
C91 "SM-1206, 10%, 10v, X7R" CAPC3216N 279.31,1243.21 r270 top value=22u
C92 "SM-0402, 10%, 10v" CAPC1005X06A#2 119.09,1123.13 r0 top value="0.1 u"
C93 "SM-1206, 10%, 10v, X7R" CAPC3216N 136.6,1243.21 r270 top value=22u
C94 "SM-1206, 10%, 10v, X7R" CAPC3216N 418.09,1243.21 r270 top value=22u
C95 "SM-0402, 10%, 10v" CAPC1005X06A#2 374.79,1123.13 r0 top value="0.1 u"
C102 "SM-0402, 10%, 10v" CAPC1005X06A#2 374.79,2880.8 r0 top value="0.1 u"
C103 "SM-1206, 10%, 10v, X7R" CAPC3216N 418.09,2760.72 r90 top value=22u
C104 "SM-0402, 10%, 10v" CAPC1005X06A#2 119.09,2880.8 r0 top value="0.1 u"
C105 "SM-1206, 10%, 10v, X7R" CAPC3216N 136.6,2760.72 r90 top value=22u
C106 "SM-1206, 10%, 10v, X7R" CAPC3216N 279.31,2760.72 r90 top value=22u
C107 "SM-0402, 10%, 10v" CAPC1005X06A#2 236.01,2880.8 r0 top value="0.1 u"
C111 "SM-1206, 10%, 10v, X7R" CAPC3216N 182.86,914.47 r0 top value=22u
C112 "SM-0402, 10%, 10v" CAPC1005X06A#2 480.1,942.03 r180 top value="0.1 u"
C113 "SM-1206, 10%, 10v, X7R" CAPC3216N 182.86,3089.46 r0 top value=22u
C114 "SM-0402, 10%, 10v" CAPC1005X06A#2 480.1,3061.91 r180 top value="0.1 u"
C128 "C0402C104K8PACTU" CAPC1005X06A#2 1849.21,3541.34 r90 top value="0.1 u"
C129 "C0402C104K8PACTU" CAPC1005X06A#2 1920.08,3561.02 r180 top value="0.1 u"
D1 "VDCIN PWR" CD1608-0603-PIN1-CATHODE -4476.38,4862.2 r0 top
D2 "XEM8370 PGOOD" CD1608-0603-PIN1-CATHODE -3417.32,4929.13 r0 top
D3 "BRK8370 PGOOD" CD1608-0603-PIN1-CATHODE -3027.56,4929.13 r0 top
D4 "D5V0FS4U10LP-7" D5V0FS4U10LP 1122.05,733.46 r180 top
FB1 "MI0603J601R-10" INDC1608X06N 1771.65,470.87 r90 top value=600
FB2 "MI0603J601R-10" INDC1608X06N 1677.17,470.87 r90 top value=600
FB3 "MI0603J601R-10" INDC1608X06N 1401.57,854.33 r180 top value=600
FB4 "BLM21PG221SN1D" RESC2012N 826.77,925.2 r180 top value=220
FID1 "FIDUCIAL" FID1MM/2MM-SS 1870.08,338.58 r90 top
FID2 "FIDUCIAL" FID1MM/2MM-SS -5418.15,408.76 r90 top
FID3 "FIDUCIAL" FID1MM/2MM-SS -5385.83,5255.91 r90 top
FID4 "FIDUCIAL" FID1MM/2MM-SS 2200.79,5287.4 r90 top
J1 "PJ-102AH" CUI-PJ102A -5791.34,4925.2 r270 top
J2 "0455580003" 0455580003 -5240.16,4070.87 r90 top
J3 "QSE-020-01-F-D-A" QSE-020-01-X-D-A-L-SYZYGY -4409.4,5511.81 r180 top locked
J4 "QSE-020-01-F-D-A" QSE-020-01-X-D-A-L-SYZYGY -2559.01,5511.81 r180 top locked
J5 "87831-1420" XILINX-JTAG 2409.45,740.16 r270 top
J6 "QSE-020-01-F-D-A" QSE-020-01-X-D-A-L-SYZYGY -629.87,5511.81 r180 top locked
J7 "QSE-020-01-F-D-A" QSE-020-01-X-D-A-L-SYZYGY 1220.52,5511.81 r180 top locked
J8 "FS1-Z38-20Z6-60" QSFP28_RECEPTACLE_SFF-8679 -4232.28,1362.2 r270 top locked
J9 "FS1-Z38-20Z6-60" QSFP28_RECEPTACLE_SFF-8679 -4232.28,2346.46 r270 top locked
J10 "RXP0" UFL-R-SMT-1 -5567.91,2738.19 r180 top
J11 "USB4120-03-C" USB4120-03-C 1122.05,890.94 r180 top
J12 "RXP0" UFL-R-SMT-1 1661.39,3190.81 r90 top
J14 "QSH-020-01-F-D-DP-A" QSH-020-01-X-D-DP-A-L-SYZYGY 2362.2,4137.35 r90 top locked
J15 "Header, 20-Pin, Single Row" HDR1X20-2MM 1023.62,59.06 r0 top
J16 "Header, 20-Pin, Single Row" HDR1X20-2MM -4251.97,59.06 r0 top
J17 "Header, 25-Pin, Single Row" HDR1X25-2MM 0,5098.43 r0 top
J30 "FS1-Z38-20Z6-60" QSFP28_RECEPTACLE_SFF-8679 1105.12,1226.38 r90 top locked
J31 "FS1-Z38-20Z6-60" QSFP28_RECEPTACLE_SFF-8679 1105.12,2210.63 r90 top locked
JP3 "SSSS811101" SSSS811101 -5571.82,3416.37 r270 top
JSO1 "Jack Screw Standoff" JSO-0515-01 -236.22,944.88 r90 top locked
JSO2 "Jack Screw Standoff" JSO-0515-01 -3110.24,944.88 r90 top locked
JSO3 "Jack Screw Standoff" JSO-0515-01 -3110.24,3858.27 r90 top locked
JSO4 "Jack Screw Standoff" JSO-0515-01 -236.22,3858.27 r90 top locked
L1 "CIGT252010LM1R0MNE" CIGT252010 -4812.01,2771.65 r270 top value=1u
L2 "CIGT252010LM1R0MNE" CIGT252010 -5095.47,2771.65 r270 top value=1u
L3 "CIGT252010LM1R0MNE" CIGT252010 -4950.79,2771.65 r270 top value=1u
L4 "CIGT252010LM1R0MNE" CIGT252010 -4182.09,2771.65 r270 top value=1u
L5 "CIGT252010LM1R0MNE" CIGT252010 422.03,1028.65 r90 top value=1u
L6 "CIGT252010LM1R0MNE" CIGT252010 283.25,1028.65 r90 top value=1u
L7 "CIGT252010LM1R0MNE" CIGT252010 138.57,1028.65 r90 top value=1u
L8 "CIGT252010LM1R0MNE" CIGT252010 283.25,2975.29 r270 top value=1u
L9 "CIGT252010LM1R0MNE" CIGT252010 422.03,2975.29 r270 top value=1u
L10 "CIGT252010LM1R0MNE" CIGT252010 138.57,2975.29 r270 top value=1u
L11 "CIGT252010LM1R0MNE" CIGT252010 -4465.55,2771.65 r270 top value=1u
L12 "CIGT252010LM1R0MNE" CIGT252010 -4320.87,2771.65 r270 top value=1u
L13 "0530CDMCCDS-1R5MC" 0530CDMCCDS -4856.63,3572.88 r270 top value=1.5u
L14 "1267AY-3R3N=P3" 1267AY -4393.24,4241.87 r270 top value=3.3u
LOGO1 "Opal Kelly Logo" okLogo-23x5-2021 1231.68,4545 r0 top
MC1 "QTH-090-01-F-D-A" QTH-090-01-X-D -3110.24,2401.57 r90 top locked
MC2 "QTH-060-01-L-D-DP-A" QTH-060-01-X-D-DP-A -236.22,2401.57 r90 top locked
MC3 "QTH-090-01-F-D-A" QTH-090-01-X-D -1673.23,3858.27 r0 top locked
MC4 "0877584016" HDR2X20-2MM -4251.97,196.85 r0 top
MC5 "0877584016" HDR2X20-2MM 1023.62,196.85 r0 top
MC6 "Header 25X2" HDR2X25-2MM 0,4960.63 r0 top
MH1 "MTG" MTG-3.2/6.5-PTH -5511.81,196.85 r0 top
MH2 "MTG" MTG-3.2/6.5-PTH 2362.2,196.85 r0 top
MH3 "MTG" MTG-3.2/6.5-PTH 2322.83,5511.81 r0 top
MH4 "MTG" MTG-3.2/6.5-PTH -5511.81,5511.81 r0 top
Q1 "SI1922EDH-T1-GE3" SOT363-6N -3927.17,2751.97 r270 top
Q2 "SI1922EDH-T1-GE3" SOT363-6N -4366.14,4547.24 r270 top
Q3 "SI1922EDH-T1-GE3" SOT363-6N -3927.17,3175.2 r270 top
Q4 "SI1922EDH-T1-GE3" SOT363-6N -4590.55,3181.1 r270 top
QSFP1 "Pressfit" QSFP28_SINGLE_CAGE -4232.28,1362.2 r270 top locked
QSFP2 "Pressfit" QSFP28_SINGLE_CAGE -4232.28,2346.46 r270 top locked
QSFP3 "Pressfit" QSFP28_SINGLE_CAGE 1105.12,1226.38 r90 top locked
QSFP4 "Pressfit" QSFP28_SINGLE_CAGE 1105.12,2210.63 r90 top locked
R1 "CRCW040210K0FKED" RESC1005X06A -3923.23,2842.52 r0 top value="10.0 k"
R2 "CRCW0402200KFKED" RESC1005X06A -3828.74,2811.02 r180 top value="200 k"
R3 "CRCW04020000Z0ED" RESC1005X06A 1651.54,3616.9 r0 top value=0
R4 "CRCW04022K00FKED" RESC1005X06A -4377.95,4862.2 r270 top value="2.0 k"
R5 "CRCW04020000Z0ED" RESC1005X06A 1651.54,3530.28 r0 top value=0
R6 "CRCW04020000Z0ED" RESC1005X06A 1651.54,3443.67 r0 top value=0
R7 "CRCW04020000Z0ED" RESC1005X06A 1651.54,3573.59 r180 top value=0
R8 "CRCW04020000Z0ED" RESC1005X06A 1651.54,3486.98 r180 top value=0
R9 "CRCW04020000Z0ED" RESC1005X06A 1651.54,3400.36 r180 top value=0
R10 "CRCW04025K36FKED" RESC1005X06A -344.09,5277.15 r180 top value="5.36 k"
R11 "CRCW04024K02FKED" RESC1005X06A 1506.3,5277.15 r180 top value="4.02 k"
R12 "CRCW04022K00FKED" RESC1005X06A -3314.96,4929.13 r270 top value="2.0 k"
R13 "CRCW04024K75FKED" RESC1005X06A -3501.97,2728.35 r0 top value="4.75 k"
R14 "CRCW04024K75FKED" RESC1005X06A -3501.97,2692.91 r0 top value="4.75 k"
R15 "CRCW04024K75FKED" RESC1005X06A -3501.97,2657.48 r0 top value="4.75 k"
R16 "CRCW04024K75FKED" RESC1005X06A -3576.77,2584.65 r270 top value="4.75 k"
R17 "CRCW04024K75FKED" RESC1005X06A -3612.2,2584.65 r270 top value="4.75 k"
R18 "CRCW04024K75FKED" RESC1005X06A -3647.64,2584.65 r270 top value="4.75 k"
R19 "CRCW04024K75FKED" RESC1005X06A -3753.94,2919.29 r90 top value="4.75 k"
R20 "CRCW04024K75FKED" RESC1005X06A -3789.37,2919.29 r90 top value="4.75 k"
R21 "CRCW04024K75FKED" RESC1005X06A -3647.64,2919.29 r90 top value="4.75 k"
R22 "CRCW04024K75FKED" RESC1005X06A -3683.07,2919.29 r90 top value="4.75 k"
R23 "CRCW04024K75FKED" RESC1005X06A -3718.5,2919.29 r90 top value="4.75 k"
R24 "CRCW04024K75FKED" RESC1005X06A -3576.77,2919.29 r90 top value="4.75 k"
R25 "CRCW04023K01FKED" RESC1005X06A 1983.07,3545.28 r90 top value="3.01 k"
R26 "CRCW04023K01FKED" RESC1005X06A 1983.07,3470.47 r270 top value="3.01 k"
R27 "CRCW04022K94FKED" RESC1005N 2132.05,3854.29 r90 top value="2.94 k"
R28 "CRCW04024K75FKED" RESC1005X06A -3612.2,2919.29 r90 top value="4.75 k"
R29 "CRCW04024K75FKED" RESC1005X06A -3501.97,2799.21 r0 top value="4.75 k"
R30 "CRCW04024K75FKED" RESC1005X06A -3683.07,2584.65 r270 top value="4.75 k"
R31 "CRCW04024K75FKED" RESC1005X06A -3718.5,2584.65 r270 top value="4.75 k"
R32 "CRCW04024K75FKED" RESC1005X06A -3753.94,2584.65 r270 top value="4.75 k"
R33 "CRCW04024K75FKED" RESC1005X06A -3789.37,2584.65 r270 top value="4.75 k"
R34 "CRCW040210K0FKED" RESC1005X06A -3923.23,3265.75 r0 top value="10.0 k"
R35 "CRCW0402200KFKED" RESC1005X06A -3828.74,3234.25 r180 top value="200 k"
R36 "CRCW04024K75FKED" RESC1005X06A -3501.97,3155.51 r0 top value="4.75 k"
R37 "CRCW04024K75FKED" RESC1005X06A -3501.97,3120.08 r0 top value="4.75 k"
R38 "CRCW04024K75FKED" RESC1005X06A -3576.77,3007.87 r270 top value="4.75 k"
R39 "CRCW04024K75FKED" RESC1005X06A -3612.2,3007.87 r270 top value="4.75 k"
R40 "CRCW04024K75FKED" RESC1005X06A -3647.64,3007.87 r270 top value="4.75 k"
R41 "CRCW04024K75FKED" RESC1005X06A -3683.07,3007.87 r270 top value="4.75 k"
R42 "CRCW04024K75FKED" RESC1005X06A -3637.8,3342.52 r90 top value="4.75 k"
R43 "CRCW04024K75FKED" RESC1005X06A -3501.97,3190.94 r0 top value="4.75 k"
R44 "CRCW04024K75FKED" RESC1005X06A -4336.61,3344.49 r90 top value="4.75 k"
R45 "CRCW04024K75FKED" RESC1005X06A -4372.05,3344.49 r90 top value="4.75 k"
R46 "CRCW04024K75FKED" RESC1005X06A -3602.36,3342.52 r90 top value="4.75 k"
R47 "CRCW04024K75FKED" RESC1005X06A -3501.97,3226.38 r0 top value="4.75 k"
R48 "CRCW04024K75FKED" RESC1005X06A -3718.5,3007.87 r270 top value="4.75 k"
R49 "CRCW04024K75FKED" RESC1005X06A -3753.94,3007.87 r270 top value="4.75 k"
R50 "CRCW04024K75FKED" RESC1005X06A -3789.37,3007.87 r270 top value="4.75 k"
R51 "CRCW04024K75FKED" RESC1005X06A -4165.35,3157.48 r0 top value="4.75 k"
R52 "CRCW04024K75FKED" RESC1005X06A -4230.31,3344.49 r90 top value="4.75 k"
R53 "CRCW04024K75FKED" RESC1005X06A -4265.75,3344.49 r90 top value="4.75 k"
R54 "CRCW040210K0FKED" RESC1005X06A -4590.55,3271.65 r0 top value="10.0 k"
R55 "CRCW0402200KFKED" RESC1005X06A -4492.13,3236.22 r180 top value="200 k"
R56 "CRCW04024K75FKED" RESC1005X06A -4165.35,3122.05 r0 top value="4.75 k"
R57 "CRCW04024K75FKED" RESC1005X06A -4230.31,3009.84 r270 top value="4.75 k"
R58 "CRCW04024K75FKED" RESC1005X06A -4265.75,3009.84 r270 top value="4.75 k"
R59 "CRCW04024K75FKED" RESC1005X06A -4301.18,3009.84 r270 top value="4.75 k"
R60 "CRCW04024K75FKED" RESC1005X06A -4336.61,3009.84 r270 top value="4.75 k"
R61 "CRCW04024K75FKED" RESC1005X06A -4372.05,3009.84 r270 top value="4.75 k"
R62 "CRCW04024K75FKED" RESC1005X06A -4407.48,3009.84 r270 top value="4.75 k"
R63 "CRCW04024K75FKED" RESC1005X06A -4442.91,3009.84 r270 top value="4.75 k"
R64 "CRCW040210R0FKED" RESC1005X06A -4780.23,3757.1 r180 top value=10
R65 "CRCW0402107KFKED" RESC1005X06A -4690.76,3902.11 r180 top value="107 k"
R66 "CRCW040224K9FKED" RESC1005X06A -4123.62,5277.15 r180 top value="24.9 k"
R67 "CRCW040218K7FKED" RESC1005X06A -2273.23,5277.15 r180 top value=18.7k
R68 "CRCW04020000Z0ED" RESC1005X06A -4690.76,3866.11 r180 top value=0
R69 "CRCW04020000Z0ED" RESC1005X06A -4432.51,3889.25 r0 top value=0
R70 "CRCW040223K7FKED" RESC1005X06A -4615.82,3885.8 r180 top value="23.7 k"
R71 "Resistor-NoLoad" RESC1005X06A -4780.2,3830.94 r180 top
R72 "CRCW040210K0FKED" RESC1005X06A -4560.84,3873.98 r90 top value="10.0 k"
R73 "CRCW04020000Z0ED" RESC1005X06A -4780.2,3793.94 r0 top value=0
R74 "CRCW04020000Z0ED" RESC1005X06A -4508.88,3889.25 r180 top value=0
R75 "CRCW040210K0FKED" RESC1005X06A -4794.57,4212.18 r270 top value="10.0 k"
R76 "CRCW04020000Z0ED" RESC1005X06A -4831.42,4211.88 r270 top value=0
R77 "CRCW0402121KFKEDC" RESC1005X06A -4828.86,4418.47 r90 top value="121 k"
R78 "CRCW040222K1FKEDC" RESC1005X06A -4865.25,4343.87 r90 top value="22.1 k"
R79 "CRCW040210K0FKED" RESC1005X06A -4815.25,4266.87 r180 top value="10.0 k"
R80 "CRCW04024K75FKED" RESC1005X06A -3566.93,3342.52 r90 top value="4.75 k"
R81 "CRCW04024K75FKED" RESC1005X06A -4407.48,3344.49 r90 top value="4.75 k"
R82 "CRCW04024K75FKED" RESC1005X06A -4442.91,3344.49 r90 top value="4.75 k"
R83 "CRCW04024K75FKED" RESC1005X06A -4301.18,3344.49 r90 top value="4.75 k"
R84 "CRCW04024K75FKED" RESC1005X06A -4165.35,3192.91 r0 top value="4.75 k"
R85 "CRCW04024K75FKED" RESC1005X06A -4165.35,3228.35 r0 top value="4.75 k"
R86 "CRCW04024K75FKED" RESC1005X06A -3501.97,2834.65 r0 top value="4.75 k"
R87 "CRCW04024K75FKED" RESC1005X06A -3744.09,3342.52 r90 top value="4.75 k"
R88 "CRCW04024K75FKED" RESC1005X06A -3779.53,3342.52 r90 top value="4.75 k"
R89 "CRCW04024K75FKED" RESC1005X06A -3501.97,2763.78 r0 top value="4.75 k"
R90 "CRCW04024K75FKED" RESC1005X06A -3673.23,3342.52 r90 top value="4.75 k"
R91 "CRCW04024K75FKED" RESC1005X06A -3708.66,3342.52 r90 top value="4.75 k"
R92 "CRCW04022K00FKED" RESC1005X06A -2921.26,4925.2 r270 top value="2.0 k"
R93 "CRCW04025K10FKEDC" RESC1005X06A 1383.86,905.51 r180 top value="5.1 k"
R94 "CRCW04025K10FKEDC" RESC1005X06A 1383.86,940.94 r0 top value="5.1 k"
R95 "CRCW040212K0FKED" RESC1005X06A 1712.6,569.29 r90 top value="12.0 k"
R96 "CRCW040210K0FKED" RESC1005X06A 1633.86,1023.62 r180 top value="10.0 k"
R97 "CRCW04020000Z0ED" RESC1005X06A 933.07,722.44 r270 top value=0
R98 "CRCW04020000Z0ED" RESC1005X06A 972.44,722.44 r270 top value=0
R99 "CRCW04020000Z0ED" RESC1005X06A 1011.81,722.44 r270 top value=0
R100 "CRCW0402100KFKED" RESC1005X06A 1299.21,590.55 r270 top value="100 k"
R101 "CRCW0402100KFKED" RESC1005X06A 1299.21,519.69 r90 top value="100 k"
R102 "CRCW04022K00FKED" RESC1005X06A 1299.21,661.42 r90 top value="2.0 k"
R103 "CRCW040210K0FKED" RESC1005X06A 1299.21,732.28 r270 top value="10.0 k"
R104 "CRCW0402100KFKED" RESC1005X06A -452.76,1145.67 r90 top value="100 k"
S1 "SW-PB" Switch-PCB-wMounts -1921.26,996.06 r0 top
TP1 "+VDCIN" TP-PTH-65/100 -5125.98,4712.6 r0 top
TP2 "VCCADC" TP-PTH-25/45 503.94,771.65 r90 top
TP3 "+1.8V" TP-PTH-65/100 1141.73,523.62 r0 top
TP4 "GNDADC" TP-PTH-25/45 503.94,633.86 r90 top
TP5 "VCCO_67_68_69" TP-PTH-65/100 -4082.68,4287.4 r90 top
TP6 "VREFP" TP-PTH-25/45 228.35,633.86 r90 top
TP7 "VCCO_64_66" TP-PTH-65/100 -4082.68,4129.92 r90 top
TP8 "VBATT" TP-PTH-25/45 228.35,771.65 r90 top
TP9 "VCCO_88_89" TP-PTH-65/100 -4082.68,4444.88 r0 top
TP10 "DGND" TP-PTH-65/100 -4082.68,3972.44 r90 top
TP11 "DGND" TP-PTH-65/100 2059.06,196.85 r90 top
TP12 "DGND" TP-PTH-65/100 1940.94,5114.17 r90 top
TP13 "DGND" TP-PTH-65/100 -5224.41,196.85 r90 top
TP14 "PWR_EN" TP-PTH-65/100 -5153.54,3543.31 r270 top
TP15 "XADC_VP" TP-PTH-25/45 826.77,633.86 r270 top
TP16 "XADC_VN" TP-PTH-25/45 826.77,771.65 r270 top
TP17 "+3.3V_TST" TP-SMD40 -4094.49,3622.05 r270 top
TP18 "+3.3V_TST_PGOOD" TP-SMD40 -4094.49,3543.31 r270 top
TP19 "+5V_TST" TP-SMD40 -4094.49,3779.53 r270 top
TP20 "+5V_SZG_PGOOD" TP-SMD40 -4094.49,3700.79 r270 top
TP21 "XEM8370_PGOOD" TP-PTH-25/45 -4212.6,4704.72 r270 top
TP22 "BRK8370_PGOOD" TP-PTH-25/45 -4212.6,4586.61 r270 top
TP23 "TESTPOINT-SMD20" TP-SMD20 -5582.97,3063.12 r270 top
TP24 "TESTPOINT-SMD20" TP-SMD20 -5557.12,3075.25 r270 top
TP25 "TESTPOINT-SMD20" TP-SMD20 1991.99,3206.06 r270 top
TP26 "TESTPOINT-SMD20" TP-SMD20 1980.65,3179.64 r270 top
U1 "SIT9120AI-2B3-XXE156.250000" SIT9120AX-XB 551.18,3204.72 r180 top
U2 "M24256-DFMN6TP" SO-G8 1385.83,3523.62 r90 top
U3 "NVT2010BS" QFN-24 -3671.26,2751.97 r90 top
U4 "SIT9120AI-2B3-XXE156.250000" SIT9120AX-XB -3492.13,685.04 r0 top
U5 "NVT2010BS" QFN-24 -3671.26,3175.2 r90 top
U6 "511JBA125M000CAGR" OSC_SMD_32x25_6pin 956.69,3204.72 r180 top
U7 "511JBA125M000CAGR" OSC_SMD_32x25_6pin 1358.27,3204.72 r180 top
U8 "NVT2010BS" QFN-24 -4334.65,3177.17 r90 top
U9 "RT6278BHGQUF" RT6278 -4658.62,3725.61 r0 top
U10 "TPS54429ERSA" TPS54429E -4669.29,4351.38 r0 top
U11 "FIN1001M5X" SOT23-5 -5570.02,2966.57 r90 top
U12 "FIN1001M5X" SOT23-5 1889.76,3192.91 r0 top
U13 "SN74AXC1T45DBVR" SOT23-6 2098.43,795.28 r270 top
U14 "FT232HQ" FT232HQ 1724.41,814.96 r90 top
U15 "SN74AXC1T45DBVR" SOT23-6 2098.43,519.69 r270 top
U16 "SN74AXC1T45DBVR" SOT23-6 2098.43,657.48 r270 top
U17 "SN74AXC1T45DBVR" SOT23-6 2098.43,933.07 r270 top
U18 "93LC56B-E/MS-CFG001" MSOP-MS8_N 1389.76,633.86 r270 top
U19 "FXMAR2102L8X" FXMAR2102L8X 1916.34,3494.09 r0 top
Y1 "ABM8-12.000MHZ-B2-T" ABM8 1535.43,543.31 r270 top

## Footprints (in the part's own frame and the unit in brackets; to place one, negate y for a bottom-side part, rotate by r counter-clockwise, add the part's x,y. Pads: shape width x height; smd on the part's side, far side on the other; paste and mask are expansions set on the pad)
0530CDMCCDS [mm]
  rect 1.9x2.5 smd: 1(-2.05,0) 2(2.05,0)
  silkscreen extent -2.8,-2.7 2.8,2.7
1267AY [mm]
  rrect0% 2.3x5.2 smd: 1(-3.1,0) 2(3.1,0)
  silkscreen extent -4.21,-4.21 4.2,4.2
0455580003 [mm]
  round 3 hole 3 unplated: 0(-4.2,7.3) 0(4.2,7.3)
  round 3 hole 1.8: 1(-4.2,0) 2(0,0) 3(4.2,0) 4(-4.2,-4.2) 5(0,-4.2) 6(4.2,-4.2)
  silkscreen extent -7,1 7,14
ABM8 [mm]
  rect 1.3x1.05 smd: 1(-1.15,-0.925) 2(1.15,-0.925) 3(1.15,0.925) 4(-1.15,0.925)
  silkscreen extent -1.98,-1.42 1.98,0.8
CAPAE9083X70N [mm] "Aluminum Electrolytic Capacitor, Body 8.30x8.30x7.00mm, IPC Medium Density"
  rect 3.6x1.65 smd: 1(-3.325,0) 2(3.325,0)
  silkscreen extent -4.25,-4.25 4.25,4.25
CAPC1005X06A#1 [mm] "Chip Capacitor, 2-Leads, Body 1.00x0.50mm, OK custom footprint"
  rect 0.52x0.55 smd mask+0.051: 1(-0.51,0) 2(0.51,0)
CAPC1005X06A#2 [mm] "Chip Capacitor, 2-Leads, Body 1.00x0.50mm, OK custom footprint"
  rect 0.52x0.55 smd: 1(-0.51,0) 2(0.51,0)
CAPC2012X14N [mm] "Chip Capacitor, 2-Leads, Body 2.00x1.25mm, IPC Medium Density"
  rect 1.25x1.4 smd: 1(-0.825,0) 2(0.825,0)
  silkscreen extent -0.6,-0.88 0.6,0.88, body extent -1.05,-0.67 1.05,0.67, height 1.4
CAPC3216N [mm] "Chip Capacitor, Body 3.2x1.6mm, IPC Medium Density"
  rect 1.3x1.8 smd: 1(-1.45,0) 2(1.45,0)
  silkscreen extent -1.2,-1.08 1.2,1.08, body extent -1.7,-0.9 1.7,0.9, height 1.35
CD1608-0603-PIN1-CATHODE [mm] "Chip Diode; Body 1.6 x 0.8 mm (LxW typ)"
  rect 1.1x1 smd: 1(-0.85,0) 2(0.85,0)
  silkscreen extent -1.58,-0.68 0.6,0.68
CIGT252010 [mm]
  rect 0.8x2 smd: 1(-1,0) 2(1,0)
CUI-PJ102A [mm] "2.1mm/5.5mm DC power jack"
  round 2.25 hole 1.5: 1(0,13.7) 2(0,7.7) 3(4.7,10.7)
  silkscreen extent -4.5,0 4.5,14.5
D5V0FS4U10LP [mm]
  rect 0.25x0.625 smd mask+0.025: 1(-1,-0.387) 2(-0.5,-0.387) 4(0.5,-0.387) 5(1,-0.387) 6(1,0.387) 7(0.5,0.387) 9(-0.5,0.387) 10(-1,0.387)
  rect 0.45x0.7 smd mask+0.025: 3(0,-0.35)
  rect 0.45x0.575 smd mask+0.025: 8(0,0.413)
  silkscreen extent -1.35,-0.9 1.35,0.55
FID1MM/2MM-SS [mm] "Fiducial 1mm copper, 2mm soldermask, single-side"
  round 1 smd paste-0.5 mask+0.5: FID?(0,0)
FT232HQ [mm]
  rrect100% 0.8x0.25 smd: 1(-4.025,2.75) 2(-4.025,2.25) 3(-4.025,1.75) 4(-4.025,1.25) 5(-4.025,0.75) 6(-4.025,0.25) 7(-4.025,-0.25) 8(-4.025,-0.75) 9(-4.025,-1.25) 10(-4.025,-1.75) 11(-4.025,-2.25) 12(-4.025,-2.75) 25(4.025,-2.75) 26(4.025,-2.25) 27(4.025,-1.75) 28(4.025,-1.25) 29(4.025,-0.75) 30(4.025,-0.25) 31(4.025,0.25) 32(4.025,0.75) 33(4.025,1.25) 34(4.025,1.75) 35(4.025,2.25) 36(4.025,2.75)
  rrect100% 0.25x0.8 smd: 13(-2.75,-4.025) 14(-2.25,-4.025) 15(-1.75,-4.025) 16(-1.25,-4.025) 17(-0.75,-4.025) 18(-0.25,-4.025) 19(0.25,-4.025) 20(0.75,-4.025) 21(1.25,-4.025) 22(1.75,-4.025) 23(2.25,-4.025) 24(2.75,-4.025) 37(2.75,4.025) 38(2.25,4.025) 39(1.75,4.025) 40(1.25,4.025) 41(0.75,4.025) 42(0.25,4.025) 43(-0.25,4.025) 44(-0.75,4.025) 45(-1.25,4.025) 46(-1.75,4.025) 47(-2.25,4.025) 48(-2.75,4.025)
  rect 6.29x6.29 smd paste-10: PAD(0,0)
  silkscreen extent -4.51,-4.06 4.06,4.51
FXMAR2102L8X [mm]
  rect 0.4x0.25 smd mask+0.051: 1(-0.605,0.5) 2(-0.605,0) 3(-0.605,-0.5) 5(0.605,-0.5) 6(0.605,0) 7(0.605,0.5)
  rect 0.25x0.45 smd mask+0.051: 4(0,-0.575) 8(0,0.575)
HDR1X20-2MM [mm] "2mm 1x20 Header"
  rect 1.3x1.3 hole 0.8: 1(-19,0)
  round 1.3 hole 0.8: 2(-17,0) 3(-15,0) 4(-13,0) 5(-11,0) 6(-9,0) 7(-7,0) 8(-5,0) 9(-3,0) 10(-1,0) 11(1,0) 12(3,0) 13(5,0) 14(7,0) 15(9,0) 16(11,0) 17(13,0) 18(15,0) 19(17,0) 20(19,0)
  silkscreen extent -20,-1 20,1
HDR1X25-2MM [mm] "2mm 1x25 Header"
  rect 1.3x1.3 hole 0.8: 1(-24,0)
  round 1.3 hole 0.8: 2(-22,0) 3(-20,0) 4(-18,0) 5(-16,0) 6(-14,0) 7(-12,0) 8(-10,0) 9(-8,0) 10(-6,0) 11(-4,0) 12(-2,0) 13(0,0) 14(2,0) 15(4,0) 16(6,0) 17(8,0) 18(10,0) 19(12,0) 20(14,0) 21(16,0) 22(18,0) 23(20,0) 24(22,0) 25(24,0)
  silkscreen extent -25,-1 25,1
HDR2X20-2MM [mm] "2mm 2x20 header"
  rect 1.3x1.3 hole 0.8: 1(-19,-1)
  round 1.3 hole 0.8: 2(-19,1) 3(-17,-1) 4(-17,1) 5(-15,-1) 6(-15,1) 7(-13,-1) 8(-13,1) 9(-11,-1) 10(-11,1) 11(-9,-1) 12(-9,1) 13(-7,-1) 14(-7,1) 15(-5,-1) 16(-5,1) 17(-3,-1) 18(-3,1) 19(-1,-1) 20(-1,1) 21(1,-1) 22(1,1) 23(3,-1) 24(3,1) 25(5,-1) 26(5,1) 27(7,-1) 28(7,1) 29(9,-1) 30(9,1) 31(11,-1) 32(11,1) 33(13,-1) 34(13,1) 35(15,-1) 36(15,1) 37(17,-1) 38(17,1) 39(19,-1) 40(19,1)
  silkscreen extent -20,-2 20,2
HDR2X25-2MM [mm] "2mm 2x25 header"
  rect 1.3x1.3 hole 0.8: 1(-24,-1)
  round 1.3 hole 0.8: 2(-24,1) 3(-22,-1) 4(-22,1) 5(-20,-1) 6(-20,1) 7(-18,-1) 8(-18,1) 9(-16,-1) 10(-16,1) 11(-14,-1) 12(-14,1) 13(-12,-1) 14(-12,1) 15(-10,-1) 16(-10,1) 17(-8,-1) 18(-8,1) 19(-6,-1) 20(-6,1) 21(-4,-1) 22(-4,1) 23(-2,-1) 24(-2,1) 25(0,-1) 26(0,1) 27(2,-1) 28(2,1) 29(4,-1) 30(4,1) 31(6,-1) 32(6,1) 33(8,-1) 34(8,1) 35(10,-1) 36(10,1) 37(12,-1) 38(12,1) 39(14,-1) 40(14,1) 41(16,-1) 42(16,1) 43(18,-1) 44(18,1) 45(20,-1) 46(20,1) 47(22,-1) 48(22,1) 49(24,-1) 50(24,1)
  silkscreen extent -25,-2 25,2
INDC1608X06N [mm] "Chip Inductor, 2-Leads, Body 1.60x0.80mm, IPC Medium Density"
  rect 0.65x0.98 smd: 1(-0.78,0) 2(0.78,0)
  silkscreen extent -0.25,-0.69 0.25,0.69, body extent -0.88,-0.48 0.87,0.47, height 0.6
JSO-0515-01 [mil]
  round 0 hole 250 unplated: 1(0,0)
  Keep-Out Layer region: 0,-157.48 -60.27,-145.49 -111.36,-111.36 -145.49,-60.27 -157.48,0 -157.48,0 -145.49,60.27 -111.36,111.36 -60.27,145.49 0,157.48 0,157.48 60.27,145.49 111.36,111.36 145.49,60.27 157.48,0 157.48,0 145.49,-60.27 111.36,-111.36 60.27,-145.49 0,-157.48
MSOP-MS8_N [mm] "TSOP, 8-Leads, Body 3x3mm, Pitch 0.65mm, IPC Medium Density"
  rect 1.45x0.45 smd mask+0.051: 1(-2.2,0.975) 2(-2.2,0.325) 3(-2.2,-0.325) 4(-2.2,-0.975) 5(2.2,-0.975) 6(2.2,-0.325) 7(2.2,0.325) 8(2.2,0.975)
  silkscreen extent -2.92,-1.57 1.52,1.57, body extent -1.55,-1.55 1.55,1.55, height 1.1
MTG-3.2/6.5-PTH [mm] "Mounting hole, 3.2mm ID, 6.5mm OD, plated"
  round 6.5 hole 3.2: 1(0,0)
